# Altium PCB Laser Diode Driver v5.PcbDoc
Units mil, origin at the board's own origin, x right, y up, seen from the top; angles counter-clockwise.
Board outline 12450 x 4500 mil, 6 copper layers (Top Layer, Internal Plane 1, Internal Plane 2, Internal Plane 3, Internal Plane 4, Bottom Layer); 217 components, 97 nets, 592 pads, 132 vias.
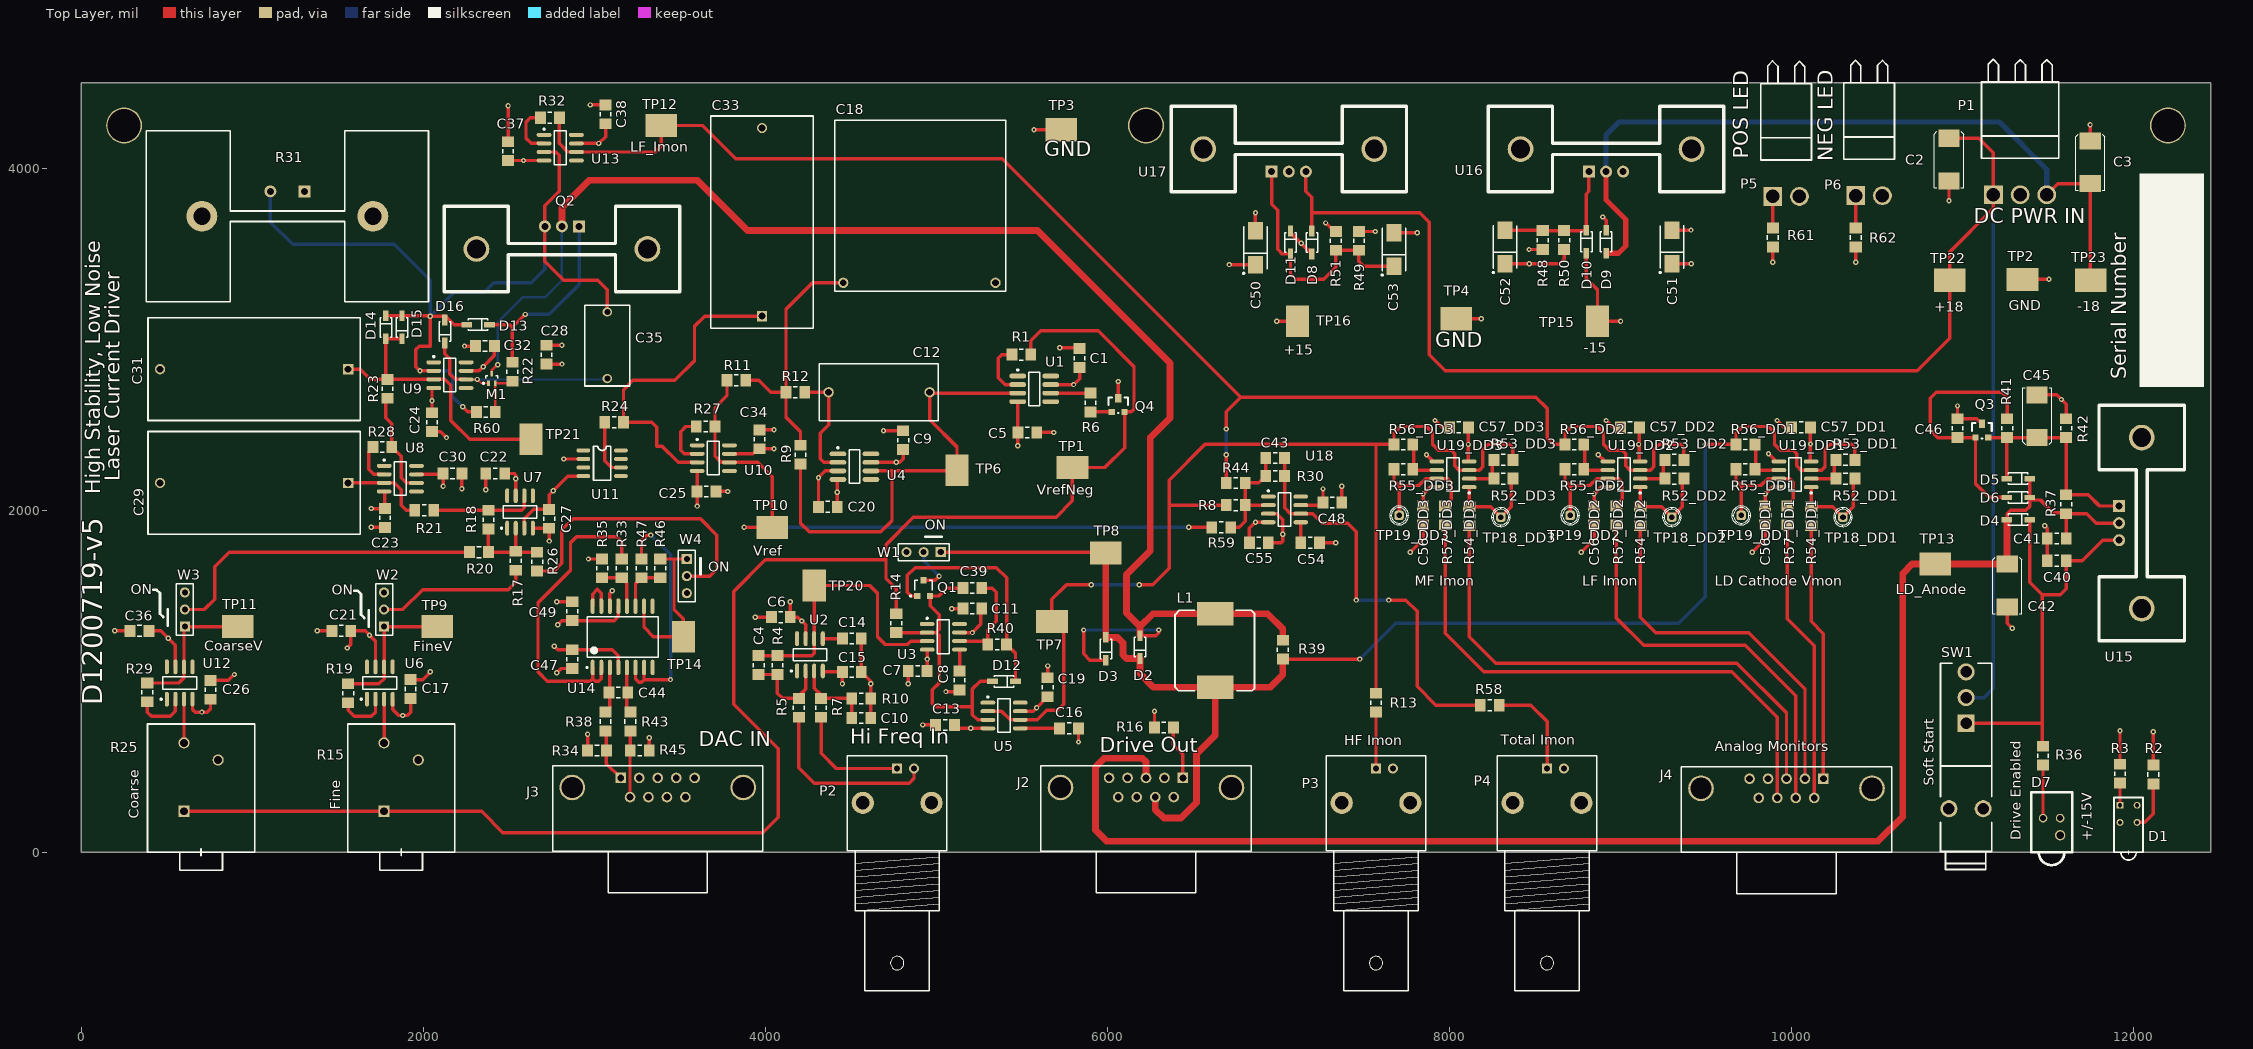
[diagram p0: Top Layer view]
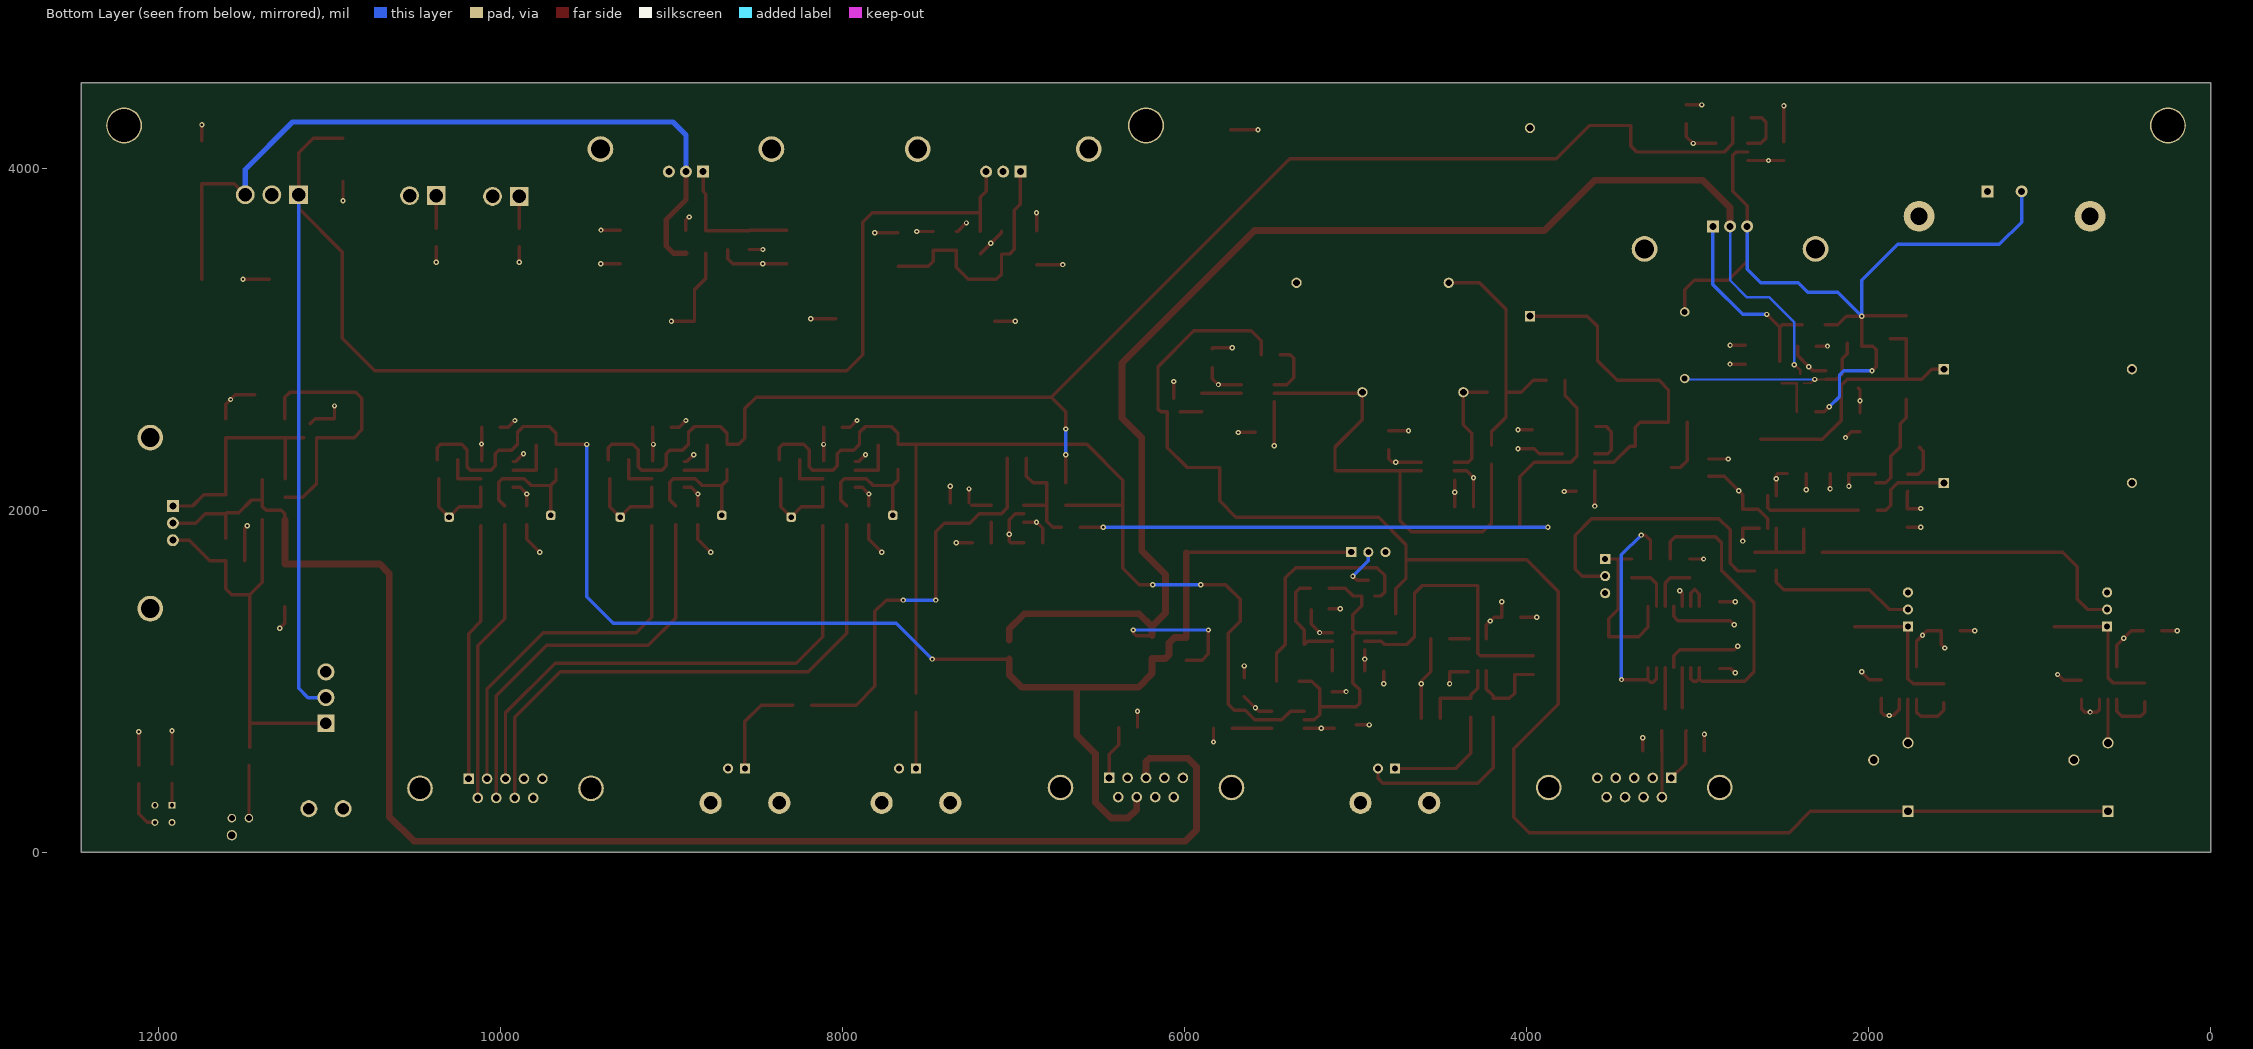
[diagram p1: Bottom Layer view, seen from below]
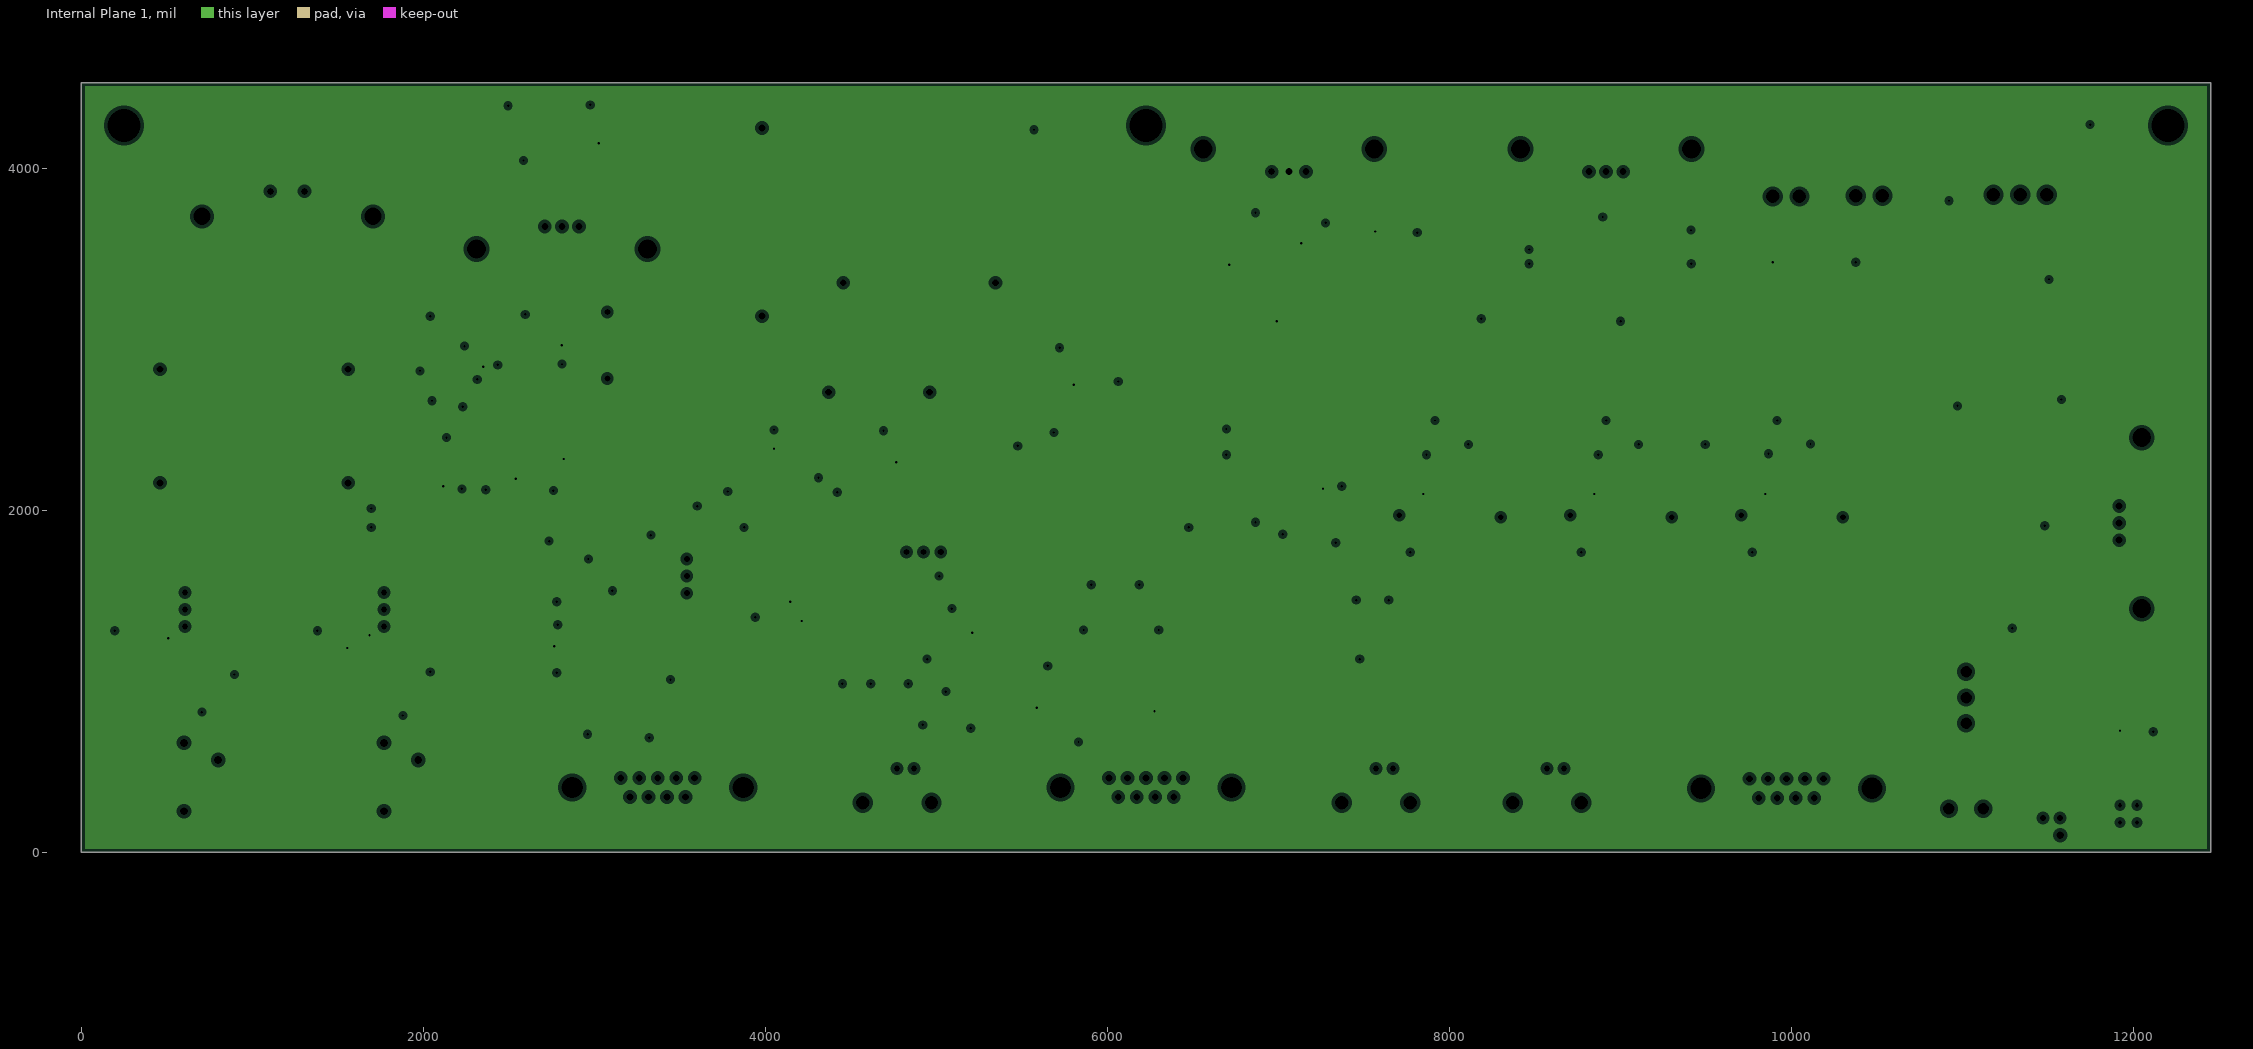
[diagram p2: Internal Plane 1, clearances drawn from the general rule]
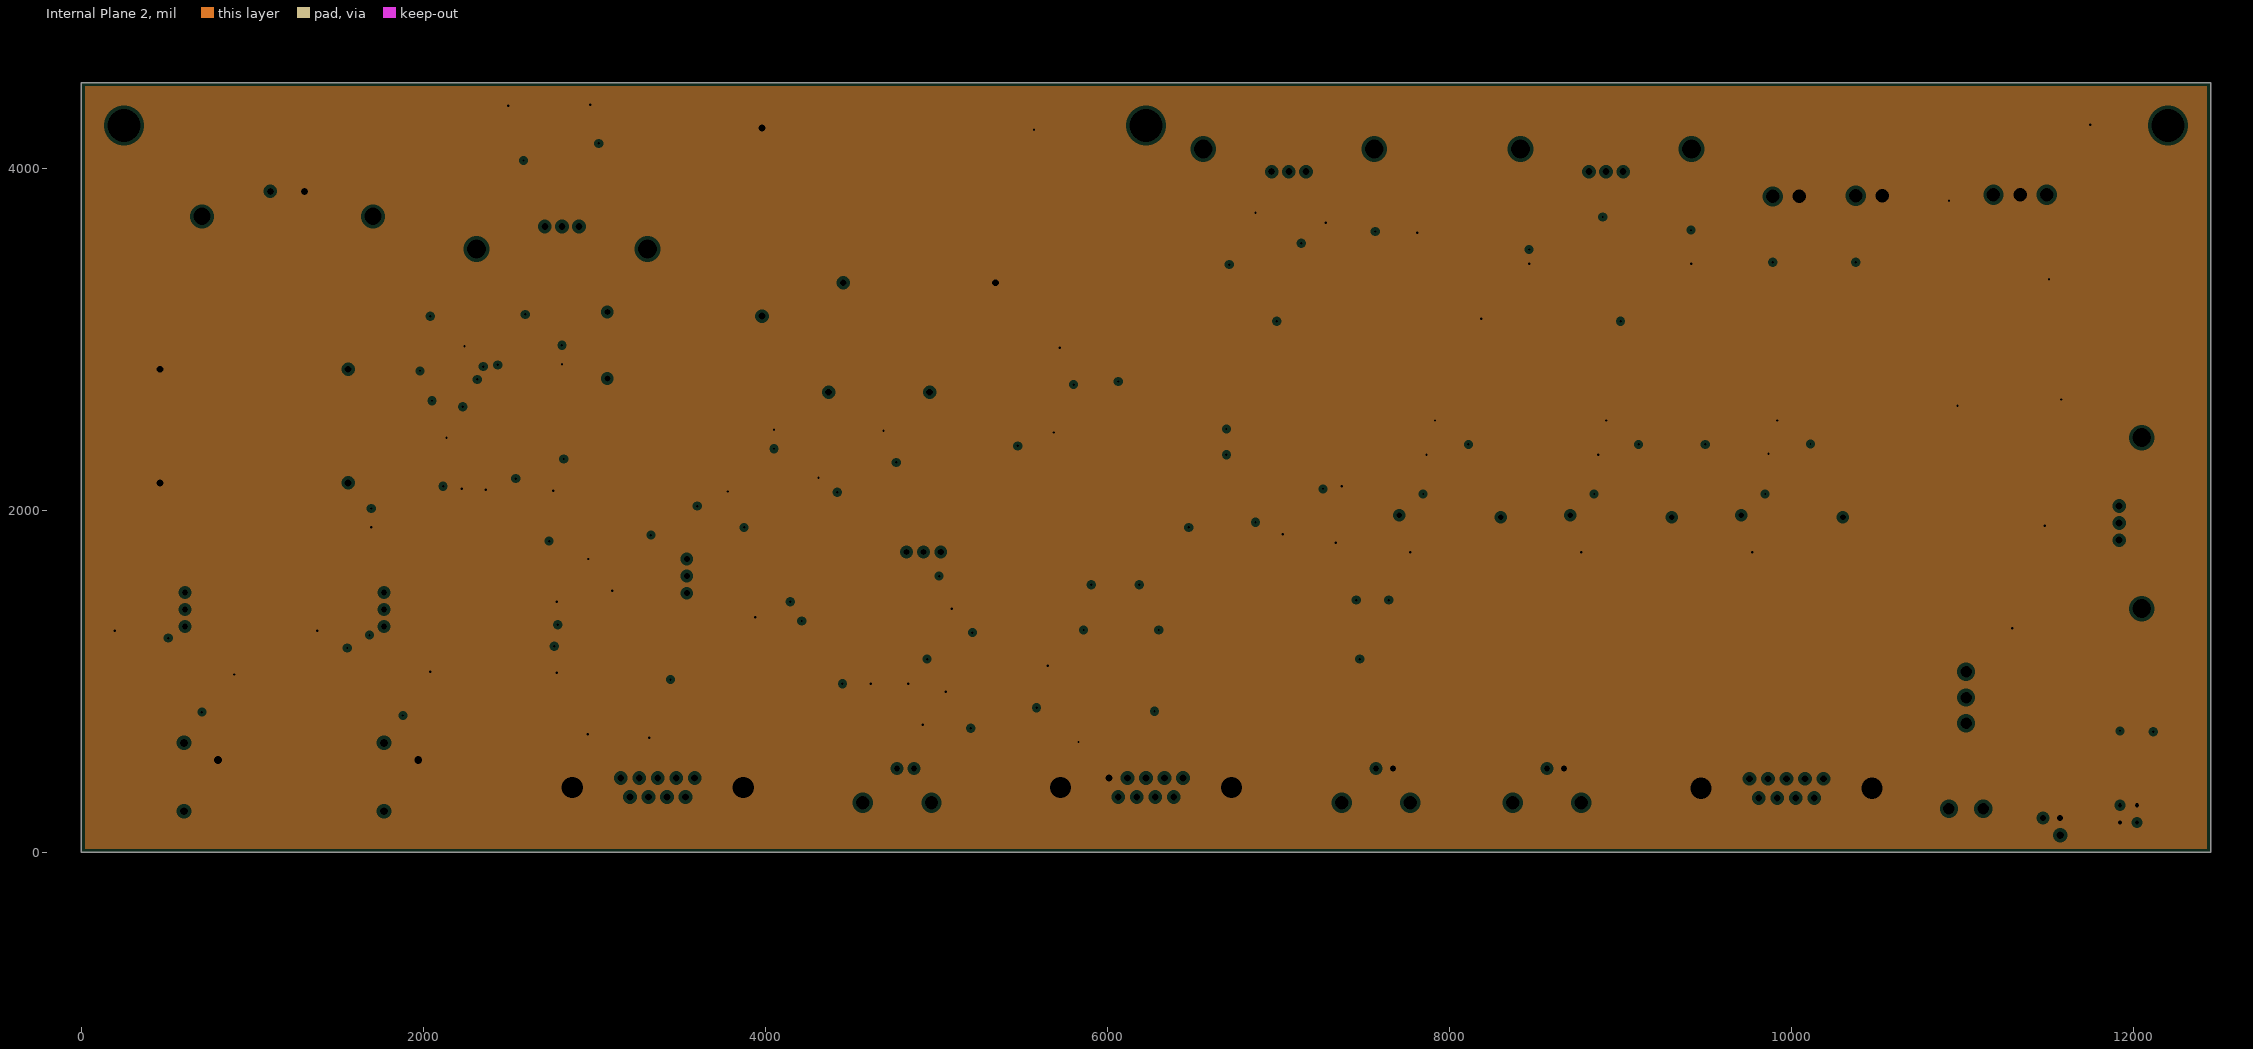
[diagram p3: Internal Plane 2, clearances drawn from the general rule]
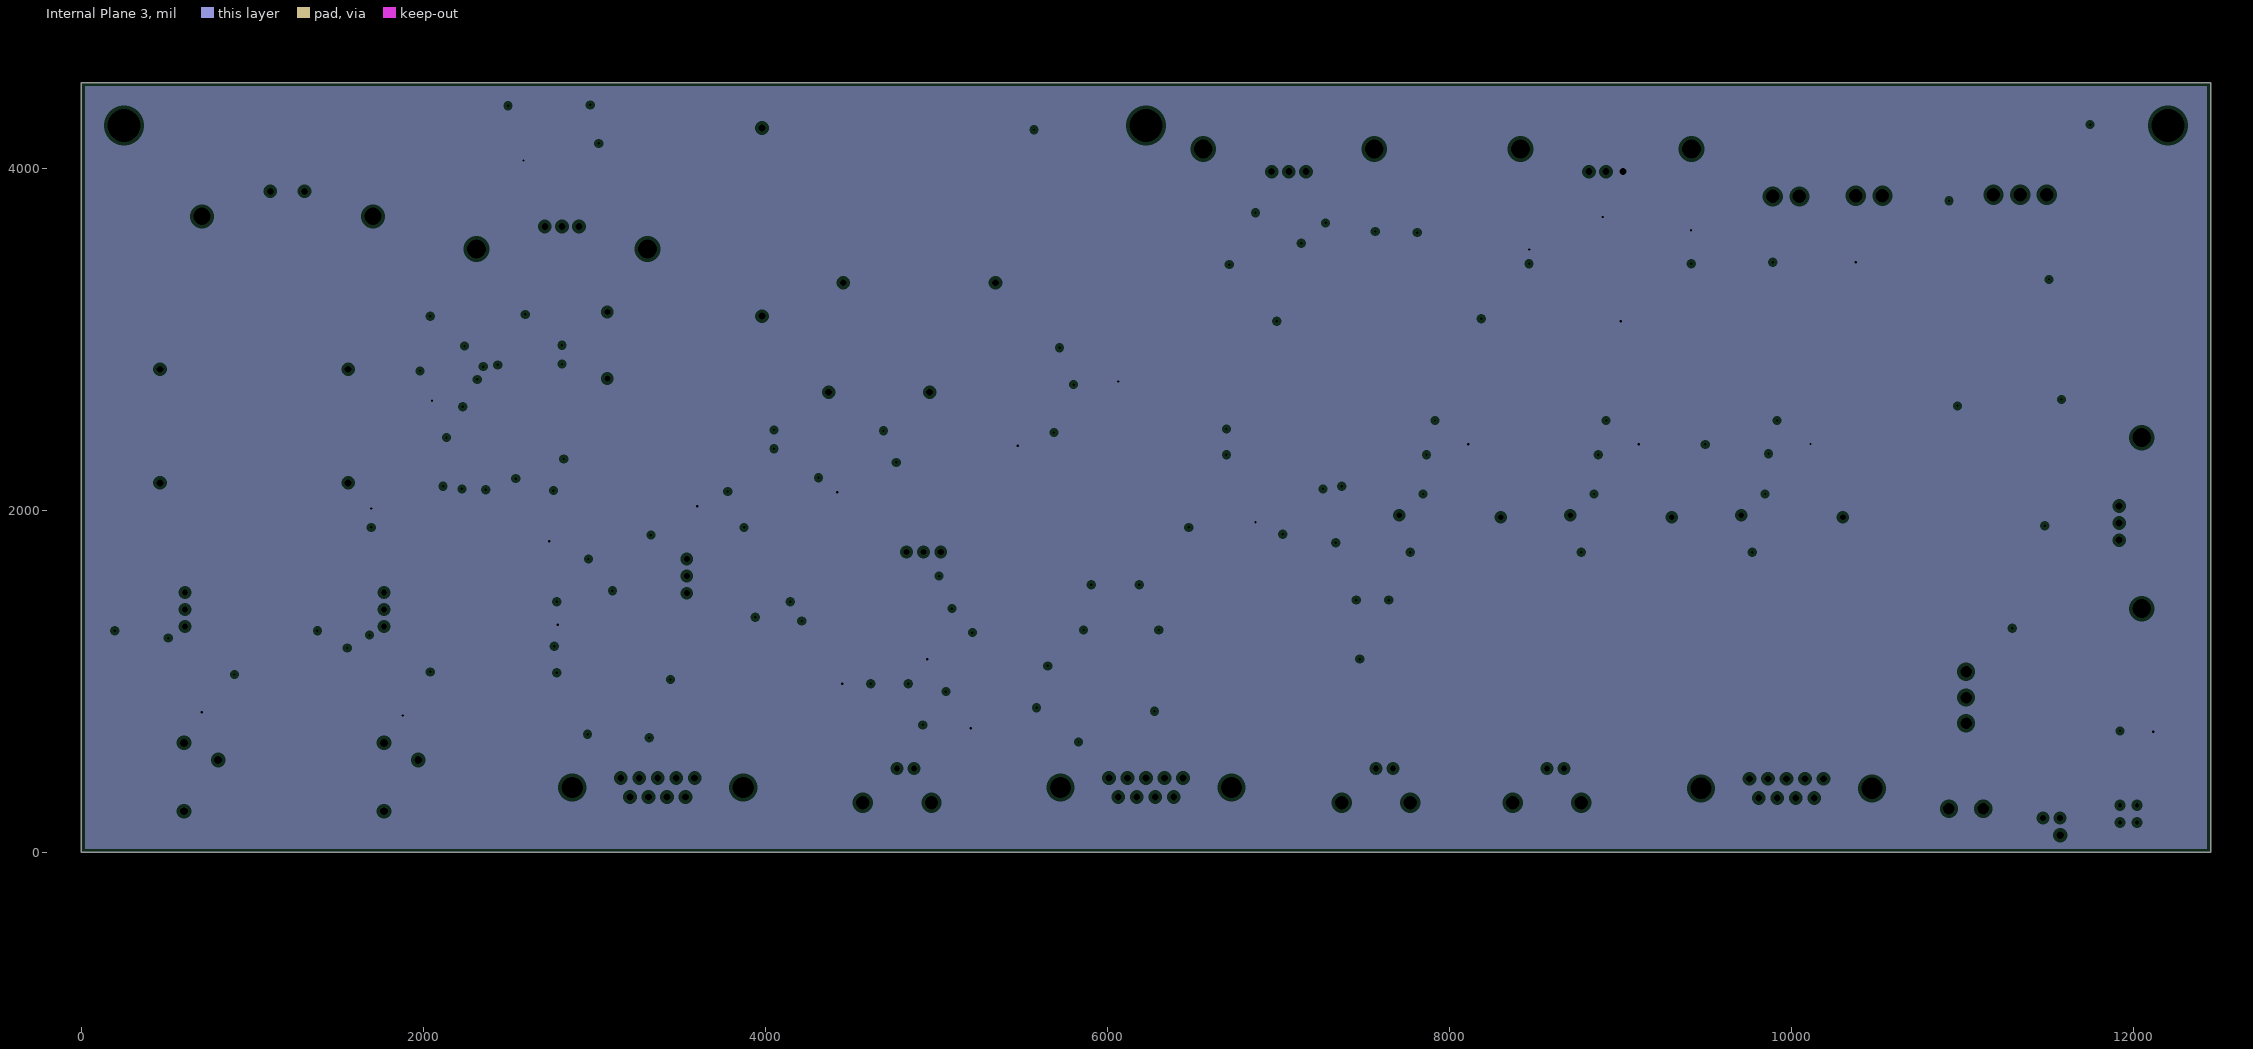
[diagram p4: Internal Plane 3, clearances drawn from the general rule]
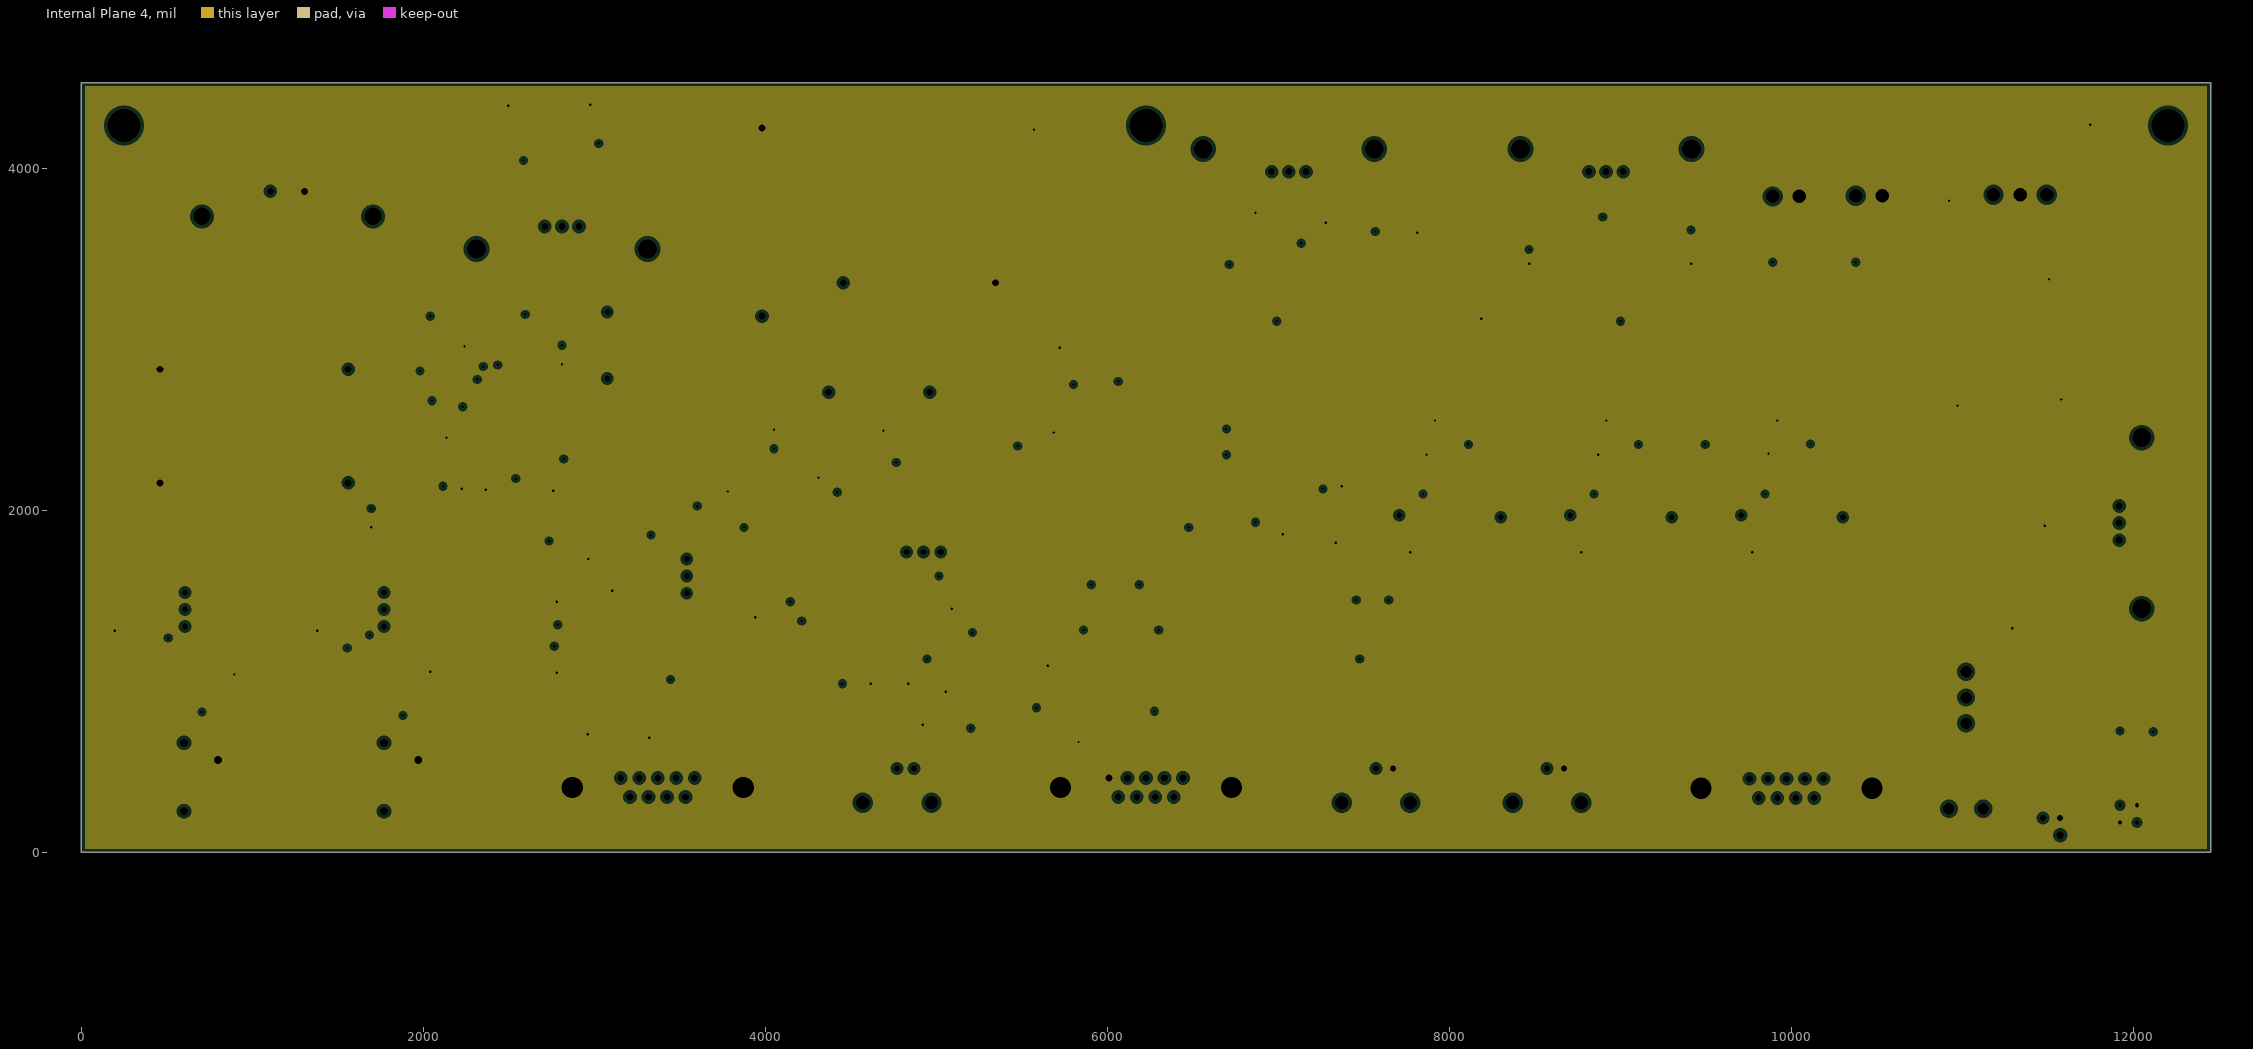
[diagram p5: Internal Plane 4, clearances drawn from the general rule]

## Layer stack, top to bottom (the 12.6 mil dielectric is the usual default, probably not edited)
Top Layer: signal copper 1.4
Dielectric: core 12.6, FR-4, Dk 4.8
Internal Plane 1: plane copper 1.4, net +15
Dielectric: prepreg 12.6, FR-4, Dk 4.8
Internal Plane 2: plane copper 1.4, net GND
Dielectric: core 12.6, FR-4, Dk 4.8
Internal Plane 3: plane copper 1.4, net -15
Dielectric: prepreg 12.6, FR-4, Dk 4.8
Internal Plane 4: plane copper 1.4, net GND
Dielectric: core 12.6, FR-4, Dk 4.8
Bottom Layer: signal copper 1.4

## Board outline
0,0 12450,0 12450,4500 0,4500

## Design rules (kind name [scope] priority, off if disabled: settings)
Clearance [All] p1: gap=10
Height [All] p1: minheight=0 maxheight=2000 prefheight=500
HoleSize [All] p1: absolutevalues=TRUE maxlimit=200 minlimit=14 maxpercent=80.000 minpercent=20.000
MinimumSolderMaskSliver [All] p1: minsoldermaskwidth=5
PlaneClearance [All] p1: clearance=20
PlaneConnect [All] p1: planeconnectstyle=Relief reliefexpansion=20 reliefentries=4 reliefconductorwidth=10 reliefairgap=10
PolygonConnect [All] p1: connectstyle=Relief reliefconductorwidth=10 reliefentries=4 polygonreliefangle="90 Angle" airgapwidth=10
RoomDefinition "Laser Diode Driver v5" [InComponentClass('Laser Diode Driver v5')] p1 off: confinementstyle=ConfineIn formatcopy=TRUE lockcomponents=FALSE outline 10015,3275 10245,3275 10245,3470 10015,3470
RoomDefinition DD3 [InComponentClass('DD3')] p2: confinementstyle=ConfineIn formatcopy=TRUE lockcomponents=FALSE outline 7555,1655 8430,1655 8430,2555 7555,2555
RoomDefinition DD2 [InComponentClass('DD2')] p3: confinementstyle=ConfineIn formatcopy=TRUE lockcomponents=FALSE outline 8555,1655 9430,1655 9430,2555 8555,2555
RoomDefinition DD1 [InComponentClass('DD1')] p4: confinementstyle=ConfineIn formatcopy=TRUE lockcomponents=FALSE outline 9555,1655 10430,1655 10430,2555 9555,2555
RoutingVias [All] p1: holewidth=14 width=31 viastyle="Through Hole" minholewidth=14 minwidth=31 maxholewidth=50 maxwidth=50
SilkscreenOverComponentPads [All] p1: minsilkscreentomaskgap=5
SolderMaskExpansion [All] p1: expansion=4
Width [All] p1: maxlimit=100 minlimit=10 preferedwidth=20
22 further rules are at their usual default settings.

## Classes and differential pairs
channel class DiffDriver: DD1 DD2 DD3
component class "Laser Diode Driver v5": C1 C2 C3 C4 C5 C6 C7 C8 C9 C10 C11 C12 C13 C14 C15 C16 C17 C18 C19 C20 C21 C22 C23 C24 C25 C26 C27 C28 C29 C30 C31 C32 C33 C34 C35 C36 C37 C38 C39 C40 C41 C42 C43 C44 C45 C46 C47 C48 C49 C50 C51 C52 C53 C54 C55 D1 D2 D3 D4 D5 D6 D7 D8 D9 D10 D11 D12 D13 D14 D15 D16 J2 J3 J4 L1 M1 P1 P2 P3 P4 P5 P6 Q1 Q2 Q3 Q4 R1 R2 R3 R4 R5 R6 R7 R8 R9 R10 R11 R12 R13 R14 R15 R16 R17 R18 R19 R20 R21 R22 R23 R24 R25 R26 R27 R28 R29 R30 R31 R32 R33 R34 R35 R36 R37 R38 R39 R40 R41 R42 R43 R44 R45 R46 R47 R48 R49 R50 R51 R58 R59 R60 R61 R62 SW1 TP1 TP2 TP3 TP4 TP6 TP7 TP8 TP9 TP10 TP11 TP12 TP13 TP14 TP15 TP16 TP20 TP21 TP22 TP23 U1 U2 U3 U4 U5 U6 U7 U8 U9 U10 U11 U12 U13 U14 U15 U16 U17 U18 W1 W2 W3 W4
component class DD3: C56_DD3 C57_DD3 R52_DD3 R53_DD3 R54_DD3 R55_DD3 R56_DD3 R57_DD3 TP18_DD3 TP19_DD3 U19_DD3
component class DD2: C56_DD2 C57_DD2 R52_DD2 R53_DD2 R54_DD2 R55_DD2 R56_DD2 R57_DD2 TP18_DD2 TP19_DD2 U19_DD2
component class DD1: C56_DD1 C57_DD1 R52_DD1 R53_DD1 R54_DD1 R55_DD1 R56_DD1 R57_DD1 TP18_DD1 TP19_DD1 U19_DD1

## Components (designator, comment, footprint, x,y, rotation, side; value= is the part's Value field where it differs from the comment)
C1 "1UF" 3216[1206] 5836.46,2890 r270 top
C2 "10UF Tantalum, 35V" 7343-31 10920,4175 r90 top
C3 "10UF Tantalum, 35V" 7343-31 11745,4160 r90 top
C4 "4.7pF" 3216[1206] 3960,1095 r270 top
C5 "1UF" 3216[1206] 5531.46,2455 r180 top
C6 "1UF" 3216[1206] 4090,1375 r0 top
C7 "1UF" 3216[1206] 4890,1060 r0 top
C8 "68pF" 3216[1206] 5135,1005 r90 top
C9 "1UF" 3216[1206] 4805,2410 r90 top
C10 "4.7pF" 3216[1206] 4560,785 r180 top
C11 "1UF" 3216[1206] 5210,1425 r0 top
C12 "2.7UF" ECQ-E1275KF 4960,2690 r180 top
C13 "1UF" 3216[1206] 5050,745 r0 top
C14 "27pF" 3216[1206] 4505,1250 r180 top
C15 "1UF" 3216[1206] 4505,1055 r180 top
C16 "68pF" 3216[1206] 5775,725 r180 top
C17 "1UF" 3216[1206] 1925,955 r270 top
C18 "10UF" ECQ-E1106KF_Side 4455,3330 r0 top
C19 "1UF" 3216[1206] 5650,965 r270 top
C20 "1UF" 3216[1206] 4365,2020 r180 top
C21 "1UF" 3216[1206] 1520,1295 r0 top
C22 "1UF" 3216[1206] 2420,2215 r0 top
C23 "1UF" 3216[1206] 1775,1955 r90 top
C24 "1UF" 3216[1206] 2050,2515 r90 top
C25 "1UF" 3216[1206] 3655,2110 r180 top
C26 "1UF" 3216[1206] 755,950 r270 top
C27 "1UF" 3216[1206] 2735,1950 r270 top
C28 "100nF" 3216[1206] 2720,2910 r90 top
C29 "20uF" AmCap_20UF 1560,2160 r180 top
C30 "1UF" 3216[1206] 2170,2215 r180 top
C31 "20uF" AmCap_20UF 1560,2825 r180 top
C32 "1UF" 3216[1206] 2360,2960 r0 top
C33 "20uF" AmCap_20UF 3980,3135 r90 top
C34 "1UF" 3216[1206] 3965,2415 r270 top
C35 "1UF" ECQ-E1105KF 3075,3160 r270 top
C36 "1UF" 3216[1206] 340,1295 r0 top
C37 "1UF" 3216[1206] 2495,4100 r270 top
C38 "1UF" 3216[1206] 3065,4315 r270 top
C39 "100pF" 3216[1206] 5210,1545 r180 top
C40 "1UF" 3216[1206] 11550,1705 r180 top
C41 "100nF" 3216[1206] 11550,1835 r180 top
C42 "22uF" 7343-31 11260,1685 r90 top
C43 "4.7pF" 3216[1206] 6980,2305 r180 top
C44 "5.6nF" 3216[1206] 3140,935 r180 top
C45 "10uF" 7343-31 11435,2425 r270 top
C46 "1UF" 3216[1206] 10970,2480 r90 top
C47 "1UF" 3216[1206] 2870,1130 r270 top
C48 "1UF" 3216[1206] 7315,2045 r180 top
C49 "1UF" 3216[1206] 2870,1410 r90 top
C50 "10UF Tantalum, 35V" 6032 6865,3535 r90 top
C51 "10UF Tantalum, 35V" 6032 9300,3540 r90 top
C52 "10UF Tantalum, 35V" 6032 8325,3540 r90 top
C53 "10UF Tantalum, 35V" 6032 7675,3525 r90 top
C54 "68pF" 3216[1206] 7185,1810 r180 top
C55 "1UF" 3216[1206] 6885,1810 r180 top
C56_DD1 "1UF" 3216[1206] 9845,1970 r90 top (schematic designator C56)
C56_DD2 "1UF" 3216[1206] 8845,1970 r90 top (schematic designator C56)
C56_DD3 "1UF" 3216[1206] 7845,1970 r90 top (schematic designator C56)
C57_DD1 "1UF" 3216[1206] 10055,2485 r0 top (schematic designator C57)
C57_DD2 "1UF" 3216[1206] 9055,2485 r0 top (schematic designator C57)
C57_DD3 "1UF" 3216[1206] 8055,2485 r0 top (schematic designator C57)
D1 "DUAL_LED" "MY LUMEX DUAL LED" 11970,0 r90 top
D2 "RB160M-60" SOD123 6190,1200 r270 top
D3 "RB160M-60" SOD123 5990,1190 r270 top
D4 "RB160M-60" SOD123 11325,1945 r0 top
D5 "RB160M-60" SOD123 11325,2185 r0 top
D6 "RB160M-60" SOD123 11325,2075 r0 top
D7 "LED-GREEN" LED_RA 11520,0 r0 top
D8 "RB160M-60" SOD123 7195,3565.32 r90 top
D9 "RB160M-60" SOD123 8915,3570 r90 top
D10 "RB160M-60" SOD123 8800,3570 r90 top
D11 "RB160M-60" SOD123 7070,3565.32 r90 top
D12 "RB160M-60" SOD123 5395,1000 r0 top
D13 "RB160M-60" SOD123 2320,3085 r0 top
D14 "RB160M-60" SOD123 1780,3070 r90 top
D15 "RB160M-60" SOD123 1875,3070 r270 top
D16 "RB160M-60" SOD123 2125,3045 r270 top
J2 "D Connector 9" MY_DB9F_RA 6225,435 r180 top
J3 "Male D9" MY_DB9M_RA 3370,435 r180 top
J4 "D9 Female" MY_DB9F_RA 9970,430 r180 top
L1 "Inductor" CDRH127 6630,965 r180 top
M1 "NMOS" SOT416-3L 2400,2770 r90 top
P1 "Header 3" Molex_156_RA_3 11180,3845 r90 top
P2 "BNC" "MY_BNC_RA CON" 4770,490 r90 top
P3 "BNC" "MY_BNC_RA CON" 7570,490 r90 top
P4 "BNC" "MY_BNC_RA CON" 8570,490 r90 top
P5 "Header 2" MOLEX_156_RA_2 9890,3835 r90 top
P6 "Header 2" MOLEX_156_RA_2 10375,3840 r90 top
Q1 "2N5551" SOT-23 4925,1545 r0 top
Q2 "2N6292" HS403-ND 2810,3660 r180 top
Q3 "PN2907A" "sot-23 3906" 11115,2460 r0 top
Q4 "2N2907" "sot-23 3906" 6065,2610 r0 top
R1 "499" 3216[1206] 5496.46,2910 r180 top
R2 "2K" 3216[1206] 12115,455 r270 top
R3 "2K" 3216[1206] 11920,460 r90 top
R4 "1K" 3216[1206] 4070,1095 r270 top
R5 "1K" 3216[1206] 4195,845 r270 top
R6 "1K" 3216[1206] 5900,2630 r90 top
R7 "1K" 3216[1206] 4325,845 r90 top
R8 "499k" 3216[1206] 6750,2030 r180 top
R9 "43.2K" 3216[1206] 4205,2325 r270 top
R10 "1K" 3216[1206] 4560,900 r0 top
R11 "43.2K" 3216[1206] 3830,2760 r0 top
R12 "24.3K" 3216[1206] 4175,2690 r180 top
R13 "499" 3216[1206] 7570,875 r270 top
R14 "4.99k" 3216[1206] 4765,1340 r270 top
R15 "10k" "Bournes Pot" 1870,0 r0 top
R16 "2.1k" 3216[1206] 6330,730 r180 top
R17 "100k" 3216[1206] 2540,1705 r90 top
R18 "10K" 3216[1206] 2380,1945 r90 top
R19 "499" 3216[1206] 1560,930 r270 top
R20 "10K" 3216[1206] 2325,1755 r0 top
R21 "10K" 3216[1206] 2005,2000 r180 top
R22 "1k" 3216[1206] 2520,2810 r270 top
R23 "10K" 3216[1206] 1790,2710 r90 top
R24 "10K" 3216[1206] 3115,2515 r0 top
R25 "10k" "Bournes Pot" 700,0 r0 top
R26 "10K" 3216[1206] 2665,1700 r90 top
R27 "499" 3216[1206] 3650,2490 r180 top
R28 "499" 3216[1206] 1760,2370 r180 top
R29 "499" 3216[1206] 385,935 r270 top
R30 "10K" 3216[1206] 6980,2200 r180 top
R31 "Res3" "AAVID TO220 Heatsink_2pin" 1205,3865 r180 top
R32 "499" 3216[1206] 2740,4295 r180 top
R33 "3.01K" 3216[1206] 3160,1660 r90 top
R34 "100K OHM" 3216[1206] 3015,595 r0 top
R35 "3.01k" 3216[1206] 3045,1660 r90 top
R36 "2K" 3216[1206] 11470,565 r270 top
R37 "249" 3216[1206] 11605,2035 r270 top
R38 "1K" 3216[1206] 3065,765 r270 top
R39 "OMIT" 3216[1206] 7025,1185 r270 top
R40 "1k" 3216[1206] 5355,1215 r180 top
R41 "1K" 3216[1206] 11260,2480 r90 top
R42 "2.21k" 3216[1206] 11605,2480 r270 top
R43 "1K" 3216[1206] 3210,765 r270 top
R44 "10k" 3216[1206] 6750,2160 r180 top
R45 "100K OHM" 3216[1206] 3265,595 r0 top
R46 "3.01k" 3216[1206] 3385,1660 r270 top
R47 "3.01K" 3216[1206] 3275,1660 r90 top
R48 "120" 3216[1206] 8545,3580 r270 top
R49 "249" 3216[1206] 7470,3575 r90 top
R50 "1.3K" 3216[1206] 8670,3580 r90 top
R51 "2.7K" 3216[1206] 7335,3575 r270 top
R52_DD1 "4.99K" 3216[1206] 10315,2185 r0 top (schematic designator R52)
R52_DD2 "4.99K" 3216[1206] 9315,2185 r0 top (schematic designator R52)
R52_DD3 "4.99K" 3216[1206] 8315,2185 r0 top (schematic designator R52)
R53_DD1 "4.99K" 3216[1206] 10315,2295 r180 top (schematic designator R53)
R53_DD2 "4.99K" 3216[1206] 9315,2295 r180 top (schematic designator R53)
R53_DD3 "4.99K" 3216[1206] 8315,2295 r180 top (schematic designator R53)
R54_DD1 "0 Ohm" 3216[1206] 10115,1965 r270 top (schematic designator R54)
R54_DD2 "0 Ohm" 3216[1206] 9115,1965 r270 top (schematic designator R54)
R54_DD3 "0 Ohm" 3216[1206] 8115,1965 r270 top (schematic designator R54)
R55_DD1 "4.99K" 3216[1206] 9730,2240 r180 top (schematic designator R55)
R55_DD2 "4.99K" 3216[1206] 8730,2240 r180 top (schematic designator R55)
R55_DD3 "4.99K" 3216[1206] 7730,2240 r180 top (schematic designator R55)
R56_DD1 "4.99K" 3216[1206] 9730,2385 r0 top (schematic designator R56)
R56_DD2 "4.99K" 3216[1206] 8730,2385 r0 top (schematic designator R56)
R56_DD3 "4.99K" 3216[1206] 7730,2385 r0 top (schematic designator R56)
R57_DD1 "0 Ohm" 3216[1206] 9975,1970 r270 top (schematic designator R57)
R57_DD2 "0 Ohm" 3216[1206] 8975,1970 r270 top (schematic designator R57)
R57_DD3 "0 Ohm" 3216[1206] 7975,1970 r270 top (schematic designator R57)
R58 "499" 3216[1206] 8235,860 r0 top
R59 "499k" 3216[1206] 6665,1900 r180 top
R60 "1k" 3216[1206] 2365,2575 r180 top
R61 "2K" 3216[1206] 9890,3595 r270 top
R62 "2K" 3216[1206] 10375,3595 r270 top
SW1 "SPDT" my_ra_spdt 11020,755 r90 top
TP1 "TESTPT" smt_tp 5795,2250 r180 top
TP2 "TESTPT" smt_tp 11350,3350 r180 top
TP3 "TESTPT" smt_tp 5730,4225 r180 top
TP4 "TESTPT" smt_tp 8040,3120 r180 top
TP6 "TESTPT" smt_tp 5120,2235 r90 top
TP7 "TESTPT" smt_tp 5675,1350 r180 top
TP8 "TESTPT" smt_tp 5990,1750 r180 top
TP9 "TESTPT" smt_tp 2080,1320 r180 top
TP10 "TESTPT" smt_tp 4040,1900 r0 top
TP11 "TESTPT" smt_tp 915,1320 r180 top
TP12 "TESTPT" smt_tp 3390,4250 r0 top
TP13 "TESTPT" smt_tp 10840,1685 r180 top
TP14 "TESTPT" smt_tp 3520,1260 r90 top
TP15 "TESTPT" smt_tp 8865,3105 r270 top
TP16 "TESTPT" smt_tp 7110,3105 r90 top
TP18_DD1 "Wire Hole" TP-hole 10300,1960 r90 top (schematic designator TP18)
TP18_DD2 "Wire Hole" TP-hole 9300,1960 r90 top (schematic designator TP18)
TP18_DD3 "Wire Hole" TP-hole 8300,1960 r90 top (schematic designator TP18)
TP19_DD1 "Wire Hole" TP-hole 9705,1970 r90 top (schematic designator TP19)
TP19_DD2 "Wire Hole" TP-hole 8705,1970 r90 top (schematic designator TP19)
TP19_DD3 "Wire Hole" TP-hole 7705,1970 r90 top (schematic designator TP19)
TP20 "TESTPT" smt_tp 4285,1560 r90 top
TP21 "TESTPT" smt_tp 2630,2415 r270 top
TP22 "TESTPT" smt_tp 10925,3345 r0 top
TP23 "TESTPT" smt_tp 11750,3345 r0 top
U1 "ADOP27AQ" SO8_M 5571.46,2710 r0 top
U2 "AD829" SOIC127P600-8N 4260,1155 r90 top
U3 "AD829" SOIC127P600-8N 5040,1260 r0 top
U4 "OPA140AID" SO8_M 4520,2255 r0 top
U5 "AD829" SOIC127P600-8N 5395,800 r0 top
U6 "OP27GS" SO-8_N 1745,990 r90 top
U7 "OP27GS" SO-8_N 2565,1990 r90 top
U8 "OP27GS" SO-8_N 1865,2185 r0 top
U9 "OP27GS" SO-8_N 2155,2790 r0 top
U10 "OP27GS" SO-8_N 3695,2305 r0 top
U11 "LT1021" SO-8 3055,2290 r0 top
U12 "OP27GS" SO-8_N 575,990 r90 top
U13 "OP27GS" SO-8_N 2800,4120 r0 top
U14 "LT1125CS" SOIC127P1030-16N 3165,1260 r90 top
U15 "LM317T" HS403-ND 11915,1925 r270 top
U16 "LM337BT" HS403-ND 8915,3980 r0 top
U17 "LM317T" HS403-ND 7060,3980 r0 top
U18 "AD829" SOIC127P600-8N 7035,2005 r0 top
U19_DD1 "AD8672" SO8_N 10020,2210 r180 top (schematic designator U19)
U19_DD2 "AD8672" SO8_N 9020,2210 r180 top (schematic designator U19)
U19_DD3 "AD8672" SO8_N 8020,2210 r180 top (schematic designator U19)
W1 "Jumper" HDR1X3 5025,1755 r180 top
W2 "Jumper" HDR1X3 1770,1320 r90 top
W3 "Jumper" HDR1X3 605,1320 r90 top
W4 "Jumper" HDR1X3 3540,1715 r270 top

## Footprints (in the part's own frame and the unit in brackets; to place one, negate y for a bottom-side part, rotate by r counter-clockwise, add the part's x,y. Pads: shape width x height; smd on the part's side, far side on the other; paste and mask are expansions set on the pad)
3216[1206] [mm] "Chip Resistor; Body 3.2 x 1.6 mm (LxW typ)"
  rect 1.6x1.8 smd: 1(-1.4,0) 2(1.4,0)
  silkscreen extent -0.3,-0.8 0.3,0.8, body extent -2.29,-1.02 2.29,1.02, height 0.48
6032 [mm] "Capacitor, SM Tantalum; Body 6.0 x 3.2 mm (LxW typ)"
  rect 2.6x2.2 smd: 1(-2.5,0) 2(2.5,0)
  silkscreen extent -3.92,-1.75 3.15,1.87
7343-31 [mil]
  rect 100x125 smd: 1(0,0) 2(-250,0)
  silkscreen extent -290,-85 40,85
"AAVID TO220 Heatsink_2pin" [mil] "High Power TO220 Heatsink with two pins"
  rect 70x70 hole 40.5: 1(-100,0)
  round 70 hole 40.5: 2(100,0)
  round 180 hole 100.5: 4(-500,146) 5(500,146)
  silkscreen extent -825,-354 825,646
AmCap_20UF [mil] "American Capacitor Radial Lead 20UF, 35 volt"
  rect 60x60 hole 40: 1(0,0)
  round 60 hole 40: 2(1100,0)
  silkscreen extent -70,-300 1170,300
"Bournes Pot" [mil] "Model 83 Series Bournes Boardmount Potentiometer"
  round 65 hole 46: 1(100,540) 2(-100,640)
  rect 65x65 hole 46: 3(-100,240)
  silkscreen extent -313,-105 313,750
CDRH127 [mil] "CDRH127 series power inductor footprint."
  rect 215x135 smd: 1(0,0) 2(0,-430)
  silkscreen extent -230,-450 235,20
ECQ-E1105KF [mil] "Plastic Cap 1UF"
  round 55 hole 35: 1(0,0) 2(390,0)
  silkscreen extent -39,-132 433,132
ECQ-E1106KF_Side [mil] "Plastic Cap 10UF (On Side)"
  round 60 hole 40: 1(0,0) 2(890,0)
  silkscreen extent -50,-50 950,950
ECQ-E1275KF [mil] "Plastic Cap 2.7UF"
  round 60 hole 40: 1(0,0) 2(590.55,0)
  silkscreen extent -50,-167 645,167
HDR1X3 [mm] "Connector; Header; 3 Position"
  rect 1.5x1.5 hole 0.9: 1(0,0)
  round 1.5 hole 0.9: 2(2.54,0) 3(5.08,0)
  silkscreen extent -1.27,-1.27 6.35,1.27
HS403-ND [mil] "Aavid 513002B02500G Heatsink for TO220"
  rect 70x70 hole 40.5: 1(-100,0)
  round 70 hole 40.5: 2(0,0) 3(100,0)
  round 150 hole 110: 4(-500,132) 5(500,132)
  silkscreen extent -688,-118 688,382
LED_RA [mil]
  round 60 hole 45: 0(50,100)
  round 50 hole 35: A(-50,200) K(50,200)
  silkscreen extent -120,-75 120,350
MOLEX_156_RA_2 [mil] "2 Pin Molex, 0.156mil Spacing, Right Angle"
  rect 110x110 hole 79: 1(0,0)
  round 110 hole 79: 2(0,-156)
  silkscreen extent 213,-226 792,70
Molex_156_RA_3 [mil] "3 Pin Molex, 0.156mil Spacing, Right Angle"
  rect 110x110 hole 79: 1(0,0)
  round 110 hole 79: 2(0,-156) 3(0,-312)
  silkscreen extent 213,-382 792,70
"MY LUMEX DUAL LED" [mil] "Stacked Dual LED PCB Rt Angle"
  rect 40x40 hole 25: 1(275,50)
  round 40 hole 25: 2(275,-50) 3(175,50) 4(175,-50)
  silkscreen extent -45,-85 320,85
"MY_BNC_RA CON" [mm] "Connector; BNC Elbow"
  rect 1.5x1.5 hole 0.9: 1(0,0)
  round 1.5 hole 0.9: 2(0,-2.5)
  round 3.3 hole 2: 3(-5.1,5.1) 4(-5.1,-5.1)
  silkscreen extent -33,-7.4 1.9,7.4
MY_DB9F_RA [mil]
  rect 62x62 hole 40: 1(-216,0)
  round 62 hole 40: 2(-108,0) 3(0,0) 4(108,0) 5(216,0) 6(-162,112) 7(-54,112) 8(54,112) 9(162,112)
  round 150 hole 125: 10(-500,56) 11(500,56)
  silkscreen extent -615,-70 615,672
MY_DB9M_RA [mil]
  rect 62x62 hole 40: 1(216,0)
  round 62 hole 40: 2(108,0) 3(0,0) 4(-108,0) 5(-216,0) 6(162,112) 7(54,112) 8(-54,112) 9(-162,112)
  round 150 hole 125: 10(-500,56) 11(500,56)
  silkscreen extent -615,-70 615,672
my_ra_spdt [mil] "PCB RA SPDT"
  rect 100x100 hole 67: 1(0,0)
  round 100 hole 67: 2(150,0) 3(300,0) 4(-500,100) 5(-500,-100)
  silkscreen extent -855,-150 350,150
smt_tp [mil] "5016 Surface Mount Test Point"
  rect 185x135 smd: 1(0,0)
SO8_M [mm] "SOIC, 8-Leads, Body 4.9x3.9mm, Pitch 1.27mm, IPC Low Density"
  oval 2.5x0.7 smd: 1(-2.45,1.905) 2(-2.45,0.635) 3(-2.45,-0.635) 4(-2.45,-1.905) 5(2.45,-1.905) 6(2.45,-0.635) 7(2.45,0.635) 8(2.45,1.905)
  silkscreen extent -2.57,-2.5 0.8,2.93, body extent -2,-2.5 2,2.5, height 1.75
SO8_N [mm] "SOIC, 8-Leads, Body 4.9x3.9mm, Pitch 1.27mm, IPC Medium Density"
  oval 2.2x0.6 smd: 1(-2.4,1.905) 2(-2.4,0.635) 3(-2.4,-0.635) 4(-2.4,-1.905) 5(2.4,-1.905) 6(2.4,-0.635) 7(2.4,0.635) 8(2.4,1.905)
  silkscreen extent -2.53,-2.5 0.9,2.88, body extent -2,-2.5 2,2.5, height 1.75
SO-8 [mil] "Small Outline 8-pin IC"
  oval 80x24 smd: 1(-120,60) 2(-120,10) 3(-120,-40) 4(-120,-90) 5(100,-90) 6(100,-40) 7(100,10) 8(100,60)
  silkscreen extent -60,-115 40,85
SO-8_N [mm] "SOIC, 8-Leads, Body 4.9x3.9mm, Pitch 1.27mm, IPC Medium Density"
  oval 2.2x0.6 smd: 1(-2.4,1.905) 2(-2.4,0.635) 3(-2.4,-0.635) 4(-2.4,-1.905) 5(2.4,-1.905) 6(2.4,-0.635) 7(2.4,0.635) 8(2.4,1.905)
  silkscreen extent -2.52,-2.5 0.9,2.88, body extent -1.95,-2.45 1.95,2.45, height 1.75
SOD123 [mm] "SOD-123; 2 Leads; Body 2.7 x 1.6 mm, (LxW)"
  rect 1.6x0.8 smd: 1(-1.7,0) 2(1.7,0)
  silkscreen extent -1.45,-0.85 1.45,0.85
SOIC127P600-8N [mm] "SOIC, 8-Leads, Body 4.9x3.9mm, Pitch 1.27mm, IPC Medium Density"
  oval 2.2x0.6 smd: 1(-2.4,1.905) 2(-2.4,0.635) 3(-2.4,-0.635) 4(-2.4,-1.905) 5(2.4,-1.905) 6(2.4,-0.635) 7(2.4,0.635) 8(2.4,1.905)
  silkscreen extent -2.52,-2.5 0.9,2.88, body extent -2,-2.5 2,2.5, height 1.75
SOIC127P1030-16N [mm] "SOIC, 16-Leads, Body 10.3x7.5mm, Pitch 1.27mm, IPC Medium Density"
  oval 2.3x0.6 smd: 1(-4.55,4.445) 2(-4.55,3.175) 3(-4.55,1.905) 4(-4.55,0.635) 5(-4.55,-0.635) 6(-4.55,-1.905) 7(-4.55,-3.175) 8(-4.55,-4.445) 9(4.55,-4.445) 10(4.55,-3.175) 11(4.55,-1.905) 12(4.55,-0.635) 13(4.55,0.635) 14(4.55,1.905) 15(4.55,3.175) 16(4.55,4.445)
  silkscreen extent -4.67,-5.25 3,5.42, body extent -3.75,-5.25 3.75,5.25, height 2.65
SOT416-3L [mm] "SOT416, 3-Leads, Body 1.6x0.8mm, Pitch 0.50mm, Lead Span 1.6mm, IPC High Density"
  rect 0.8x0.4 smd: 1(-0.7,0.5) 2(-0.7,-0.5) 3(0.7,0)
  silkscreen extent -0.82,-0.9 0.45,1.37, body extent -0.45,-0.9 0.45,0.9, height 0.95
SOT-23 [mm] "SOT-23; 3 Leads; Body 3.1 x 2.5 mm, inc. leads (LxW max)"
  rect 0.9x0.95 smd: 1(-0.95,-1.175) 2(0.95,-1.175) 3(0,1.175)
  silkscreen extent -2.07,-1.3 1.3,1.18
"sot-23 3906" [mil]
  rect 36x36 smd: 1(35,-35) 2(-40,-35)
  rect 36x50 smd: 3(-2,45)
  silkscreen extent -60,-40 55,50
TP-hole [mil] "Pad for small test point"
  rrect50% 55x55 hole 33: 1(0,0)
  silkscreen extent -55,-55 55,55

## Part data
C1 C5 C9 C12 C18 C20 C56_DD1 C56_DD2 C56_DD3 C57_DD1 C57_DD2 C57_DD3: library part MYCAP
C2 C3 C29 C31 C33 C42 C45 C50 C51 C52 C53: library part "CAPACITOR POL", "Polarized Cap"
C4 C6 C7 C8 C10 C11 C13 C14 C15 C16 C17 C19 C21 C22 C23 C24 C25 C26 C27 C28 C30 C32 C34 C35 C36 C37 C38 C39 C40 C41 C43 C46 C48 C54 C55: library part Cap, "Capacitor"
C44 C47 C49: library part MYCAP, "CAP 1.0UF 50V CERAMIC F 1206"
D1: "Dual Led indicator"
D2 D3 D4 D5 D6 D12 D13 D14 D15 D16: library part "Diode 1N4001", "1 Amp General Purpose Rectifier"
D7: library part LED, "LED GREEN T1-3/4 RT ANG PCB"
D8 D9 D10 D11: library part "Diode 1N4148", "High Conductance Fast Diode"
J2: "Receptacle Assembly, 9 Position, Right Angle"
J3 J4: library part "D Connector 9", "Receptacle Assembly, 9 Position, Right Angle"
M1: library part 2SK3019, "ROHM N-Channel MOSFET"
P1: "Header, 3-Pin"
P5 P6: "Header, 2-Pin"
Q1: "NPN General Purpose Amplifier"
Q2: library part FZT649, "SOT223 NPN Silicon Planar High-Performance Transistor"
Q3: "PNP General Purpose Amplifier"
Q4: library part 2N3906, "PNP General Purpose Amplifier"
R1 R2 R3 R4 R5 R6 R7 R8 R9 R10 R11 R12 R13 R14 R16 R17 R18 R19 R20 R21 R22 R23 R24 R26 R27 R28 R29 R30 R32 R36 R37 R39 R40 R41 R42 R44 R52_DD1 R52_DD2 R52_DD3 R53_DD1 R53_DD2 R53_DD3 R54_DD1 R54_DD2 R54_DD3 R55_DD1 R55_DD2 R55_DD3 R56_DD1 R56_DD2 R56_DD3 R57_DD1 R57_DD2 R57_DD3 R58 R59 R60 R61 R62: library part Res3, "Resistor"
R15 R25: library part MPEPOT, "Potentiometer"
R31: "Resistor"
R33 R34 R35 R38 R43 R45 R46 R47: library part MYRES, "Resistor"
R48 R49 R50 R51: library part MYRES
SW1: library part MY_SPDT, "Rocker SPDT"
TP1 TP2 TP3 TP4 TP6 TP7 TP8 TP9 TP10 TP11 TP12 TP13 TP14 TP15 TP16 TP20 TP21 TP22 TP23: "PCB Testpoint"
TP18_DD1 TP18_DD2 TP18_DD3 TP19_DD1 TP19_DD2 TP19_DD3: library part TestHole, "Plated Hole to Solder Wire to"
U1: "Ultra-Low Noise, Precision Operational Amplifier"
U2 U3 U5 U18: library part OP184ES, "Video Operational Amplifier"
U4: library part ADOP27AQ, "FET Input Operational Amplifier"
U6 U7 U8 U9 U10 U12 U13: "Low-Noise, Precision Operational Amplifier"
U11: "Precision Voltage Reference"
U14: "Quad Low Noise, High-Speed Precision Operational Amplifier"
U15 U17: "Three-Terminal Adjustable Output Positive Voltage Regulator"
U16: "3-Terminal Adjustable Negative Voltage Regulator"
U19_DD1 U19_DD2 U19_DD3: library part AD826AR, "High-Speed, Low-Power Dual Operational Amplifier"
W1 W2 W3 W4: "Jumper Wire"

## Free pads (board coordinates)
  round 210 hole 193: 8(250,4250) 8(12200,4250) 9(6225,4250)

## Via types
v1: diameter 31, hole 14, Top Layer to Bottom Layer, 132 vias

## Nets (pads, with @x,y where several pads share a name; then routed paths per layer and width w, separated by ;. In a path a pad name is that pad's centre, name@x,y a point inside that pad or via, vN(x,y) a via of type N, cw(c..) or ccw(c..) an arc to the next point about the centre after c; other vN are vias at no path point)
+15: C1.2 C6.2 C9.1 C11.2 C19.2 C21.2 C22.2 C28.2 C30.2 C32.2 C34.2 C36.2 C38.2 C47.1 C48.2 C50.1 C56_DD1.2 C56_DD2.2 C56_DD3.2 D8.1 D11.2 R3.2 R16.2 R49.2 R61.2 TP16.1 U1.7 U2.7 U3.7 U4.7 U5.7 U6.7 U7.7 U8.7 U9.7 U10.7 U11.2 U12.7 U13.7 U14.4 U17.2 U18.7 U19_DD1.8 U19_DD2.8 U19_DD3.8 | length 5458.7
  Top Layer w20: C36.2 465,1295 550,1210 U12.7 ; v1(1555,1195) 1575.12,1215.12 C21.2 1660,1295 1720,1235 U6.7 ; U8.7 C30.2@2109.88,2210 ; v1(2114.88,2139.88) C30.2 ; U9.7 2325,2815 v1(2350,2840) 2415.12,2905.12 C32.2 ; C22.2 2530,2215 2540,2205 U7.7 ; C28.2 v1(2809.88,2965.12) ; v1(2765,1205) 2784.88,1185.12 C47.1 3104.88,1185.12 3140,1150 U14.4 ; v1(2820,2300) U11.2 ; U13.7 v1(3025,4145) 3065,4185 C38.2 ; U10.7 3925,2330 3954.88,2359.88 C34.2 v1(4049.88,2359.88) ; v1(4145.12,1464.88) C6.2 4190,1375 4235,1330 U2.7 ; U4.7 4785,2280 4805,2300 C9.1 ; U3.7 v1(5210,1285) 5260,1335 C11.2@5260,1419.88 ; U5.7 5565.12,825 C19.2 ; U1.7 v1(5801.46,2735) 5836.46,2770 C1.2 ; R16.2 v1(6274.88,824.88) ; v1(6711.57,3436.57) C50.1 ; v1(6990,3105) TP16.1 ; D11.2 7070,3623.39 D8.1 ; U18.7 C48.2@7244.88,2030 ; C48.2 v1(7259.88,2124.88) ; R49.2 v1(7564.88,3630.12) ; C56_DD3.2 v1(7845,2095) 7885,2135 U19_DD3.8 ; C56_DD2.2 v1(8845,2095) 8885,2135 U19_DD2.8 ; C56_DD1.2 v1(9845,2095) 9885,2135 U19_DD1.8 ; v1(9890,3450) R61.2 ; R3.2 v1(11920,710)
  other v1: 5585.12,845 507.5,1252.5 1685,1270 4212.5,1352.5 2540,2185 4765,2280 7132.5,3560.89
+18: C2.1 D8.2 P1.1 SW1.2 TP22.1 U17.3 | length 9563.8
  Top Layer w20: U17.3 7160,3865 7195,3830 7195,3735 ; D8.2 7195,3735 ; C2.1 11095,4175 11180,4090 P1.1 11180,3765 10925,3510 TP22.1 10925,3005 10735,2815 7975,2815 7880,2910 7880,3685 7825,3740 7200,3740 7195,3735
  Bottom Layer w20: SW1.2 11125,905 11180,960 P1.1
-15: C5.2 C7.2 C13.2 C15.2 C17.2 C20.1 C23.2 C24.2 C25.2 C26.2 C27.2 C37.2 C49.1 C51.2 C55.2 C57_DD1.2 C57_DD2.2 C57_DD3.2 D9.2 D10.1 Q4.3 R2.1 R48.2 R62.2 TP15.1 U1.4 U2.4 U3.4 U4.4 U5.4 U6.4 U7.4 U8.4 U9.4 U10.4 U12.4 U13.4 U14.13 U16.3 U18.4 U19_DD1.4 U19_DD2.4 U19_DD3.4 | length 4766.1
  Top Layer w20: U12.4 650,835 665,820 735,820 755,840 C26.2 ; v1(1695.12,2010.12) C23.2 1775,2105.51 U8.4 ; U6.4 1820,835 1855,800 1905,800 1925,820 C17.2 ; C24.2 2050,2704.49 U9.4 ; C37.2@2495.12,4045 U13.4 ; U7.4 C27.2@2734.37,1895.51 ; v1(2735,1820) C27.2 ; v1(2785,1330) 2809.88,1354.88 C49.1 3114.88,1354.88 3140,1380 U14.13 ; v1(3600.51,2024.49) U10.4 ; U2.4@4340.51,1055 C15.2 v1(4449.88,985.12) ; C20.1 U4.4@4420.12,2176.57 ; C7.2 U3.4@4945.12,1184.61 ; C13.2@5125.12,725 U5.4 ; v1(5475,2376.46) U1.4 ; Q4.3 v1(6063,2753) ; C55.2 6829.88,1894.88 v1(6865,1930) U18.4 ; U19_DD3.4@8110.12,2289.37 C57_DD3.2 ; v1(8464.88,3524.88) R48.2 ; D10.1 8800,3355 8865,3290 TP15.1 v1(9000,3105) ; v1(8895,3715) 8915,3695 D9.2 ; U19_DD2.4@9110.12,2289.37 C57_DD2.2 ; C51.2 v1(9411.57,3638.43) ; U19_DD1.4@10110.12,2289.37 C57_DD1.2 ; v1(10375,3450) R62.2 ; R2.1 v1(12115,705)
  other v1: 5200,725 1880,800 705,820 4945.12,1130 4420,2105 8110.12,2385 9105,2385 10110.12,2387.19 2050,2640 2585,4045
-18: C3.2 D9.1 P1.3 TP23.1 U16.2 | length 4540.7
  Top Layer w20: P1.3 11557,3910 C3.2 TP23.1@11745,3350
  Top Layer w30: D9.1 8988.07,3503.07 9030,3545 9030,3700 8915,3815 U16.2
  Bottom Layer w30: U16.2 8915,4195 8990,4270 11215,4270 11492,3993 P1.3
GND: C1.1 C2.2 C3.1 C5.1 C6.1 C7.1 C8.1 C9.2 C10.1 C11.1 C13.1 C14.1 C15.1 C16.1 C17.1 C18.2 C19.1 C20.2 C21.1 C22.1 C23.1 C24.1 C25.1 C26.1 C27.1 C28.1 C29.2 C30.1 C31.2 C32.1 C33.2 C34.1 C36.1 C37.1 C38.1 C40.2 C41.2 C42.2 C45.2 C46.2 C47.2 C48.1 C49.2 C50.2 C51.1 C52.1 C53.2 C54.1 C55.1 C56_DD1.1 C56_DD2.1 C56_DD3.1 C57_DD1.1 C57_DD2.1 C57_DD3.1 D1.2 D1.3 D7.K J2.5 J2.10 J2.11 J3.10 J3.11 J4.10 J4.11 P1.2 P3.2 P4.2 P5.2 P6.2 Q3.3 R10.2 R15.1 R25.1 R31.1 R34.1 R35.2 R42.1 R45.2 R50.1 R51.1 TP2.1 TP3.1 TP4.1 U4.3 U7.3 U11.4 U14.14 U18.3 U19_DD1.5 U19_DD2.5 U19_DD3.5 | length 8185
  Top Layer w20: v1(195,1295) C36.1 ; C26.1 860.12,1005.12 v1(895,1040) ; v1(1380,1295) C21.1 ; v1(1695.12,1899.88) C23.1 ; C17.1 1995.12,1010.12 v1@2045,1060 ; C24.1 2100.12,2459.88 v1(2135,2425) ; v1@2225.12,2119.88 C30.1 ; v1(2240,2960) C32.1 ; v1(2364.88,2120.12) C22.1 ; C37.1 v1(2495,4365) ; U7.3 2590,1950 2645.12,2005.12 C27.1 2735,2090 v1(2760,2115) 2845,2200 U11.4 ; C28.1 v1(2810.12,2854.88) ; v1(2780,1050) 2804.88,1074.88 C47.2 ; v1(2780.12,1465.12) C49.2 ; R34.1 v1(2959.88,689.88) ; v1(2964.88,1715.12) R35.2 ; v1(2974.88,4370.12) C38.1 ; U14.14 3090,1515 v1(3105,1530) ; R45.2 v1(3320.12,669.88) ; C25.1 v1(3780,2110) ; v1(3940,1375) C6.1 ; C34.1 v1(4049.88,2470.12) ; C20.2 v1(4309.88,2189.88) 4350,2230 U4.3 ; C14.1 C15.1 4615.12,1000 R10.2 C10.1 ; v1(4690.12,2465.12) C9.2 ; v1(4834.88,985.12) C7.1 ; v1(4920,745) C13.1 ; v1(5055.12,940) C8.1@5135,940 ; v1(5090,1425) C11.1 ; v1(5570,4225) TP3.1 ; C5.1 v1(5686.46,2455) ; C19.1 v1(5650,1090) ; v1(5720,2950) 5835,2950 5836.46,2948.54 C1.1 ; v1(5830.12,645.12) C16.1 ; C50.2 v1(6865,3740) ; C55.1 7015,1810 7025,1820 7025,1945 6990,1980 U18.3 ; C54.1 v1(7335,1810) ; v1(7275,3680) 7324.88,3630.12 R51.1 ; C48.1 v1(7370.12,2139.88) ; C53.2 v1(7811.57,3623.43) ; v1(7770,1755) 7845,1830 C56_DD3.1 ; v1(7865,2325) 7905,2285 U19_DD3.5 ; v1(7915,2525) 7955,2485 C57_DD3.1 ; TP4.1 v1(8185,3120) ; C52.1 8641.57,3441.57 8670,3470 R50.1 ; v1(8770,1755) 8845,1830 C56_DD2.1 ; v1(8870,2325) 8910,2285 U19_DD2.5 ; v1(8915,2525) 8955,2485 C57_DD2.1 ; C51.1 v1(9413.43,3441.57) ; v1(9770,1755) 9845,1830 C56_DD1.1 ; v1(9865,2330) 9910,2285 U19_DD1.5 ; v1(9915,2525) 9955,2485 C57_DD1.1 ; v1(10920,3810) C2.2 ; v1(10970,2610) C46.2 11082.88,2535.12 Q3.3 ; C42.2 11260,1340 v1(11290,1310) ; TP2.1 v1(11505,3350) ; C45.2 11550,2675 11605,2620 R42.1 ; v1(11480,1910) 11494.88,1895.12 C41.2 C40.2 ; C3.1 v1(11745,4255)
  other v1: 4615.12,985 2040,1055 7025,1860 2225.12,2125 11577.5,2647.5 8465,3441.57
HF_IMON: R8.2 R13.1 R53_DD3.1 R56_DD3.1 TP7.1 U5.2 U5.6 U19_DD3.3 | length 6771
  Top Layer w20: U5.2 5380,825 5430,775 U5.6 5590,775 5645,830 5710,830 5745,865 5745,1280 TP7.1 5675,1480 5760,1565 v1(5905,1565) ; v1(6185,1565) 6265,1565 6360,1660 6360,2175 6570,2385 7570,2385 ; 6365,2030 R8.2 ; R13.1 7570,2385 ; R53_DD3.1 8370.12,2364.88 8350,2385 8225,2385 8195,2355 8195,2255 8175,2235 U19_DD3.3 8055,2235 8030,2260 8030,2330 8010,2350 7935,2350 7900,2385 7900,2455 7865,2490 7715,2490 7674.88,2449.88 R56_DD3.1 7570,2385
  Bottom Layer w20: v1(5905,1565) v1(6185,1565)
LD_CATHODE: D2.2 D3.1 J2.7 L1.1 R39.2 R53_DD1.1 R56_DD1.1 TP8.1 U19_DD1.3 W1.1 | length 8768.9
  Top Layer w20: W1.1 TP8.1@5985,1755 ; R39.2 7474.88,1129.88 v1(7475,1130) ; v1(9495,2385) R56_DD1.1 9674.88,2449.88 9715,2490 9865,2490 9900,2455 9900,2385 9935,2350 10010,2350 10030,2330 10030,2260 10055,2235 U19_DD1.3 10175,2235 10195,2255 10195,2355 10225,2385 10350,2385 10370.12,2364.88 R53_DD1.1
  Top Layer w40: TP8.1 D3.1 6058.07,1256.93 6090,1225 6090,1155 6111.93,1133.07 D2.2 6190,1045 6270,965 L1.1 ; J2.7 6279,251 6330,200 6430,200 6520,290 6520,575 6630,685 L1.1 ; R39.2 7025,1040 6950,965 L1.1
  Bottom Layer w20: v1(7475,1130) 7685,1340 9340,1340 9495,1495 v1(9495,2385)
LF_IMON: R32.1 R44.2 R53_DD2.1 R56_DD2.1 TP12.1 U13.6 U19_DD2.3 | length 8758.6
  Top Layer w20: R32.1 2795.12,4144.88 2845,4095 U13.6 3355,4095 3390,4130 TP12.1 3630,4250 3825,4055 5385,4055 6780,2660 ; R44.2 6694.88,2324.88 v1(6695,2325) ; v1(6695,2475) 6695,2575 6780,2660 ; R53_DD2.1 9370.12,2364.88 9350,2385 9225,2385 9195,2355 9195,2255 9175,2235 U19_DD2.3 9055,2235 9030,2260 9030,2330 9010,2350 8935,2350 8900,2385 8900,2455 8865,2490 8715,2490 8674.88,2449.88 R56_DD2.1 8605,2385 8570,2420 8570,2595 8505,2660 6780,2660
  Bottom Layer w20: v1(6695,2325) v1(6695,2475)
NetC4_1: C4.1 R4.1 TP20.1 U2.6 U3.3 | length 1687.2
  Top Layer w20: C4.1 R4.1 4270.12,1150.12 4285,1165 U2.6 TP20.1 4610,1560 4655,1515 4655,1260 4700,1215 4830,1215 4850,1235 U3.3
NetC4_2: C4.2 R4.2 R5.1 U2.2 | length 534.2
  Top Layer w20: C4.2 R4.2 4070,930 4099.88,900.12 R5.1 4195,915 4235,955 U2.2
NetC8_2: C8.2 U3.5 | length 124.4
  Top Layer w20: C8.2 U3.5@5135,1184.49
NetC10_2: C10.2 R7.2 R10.1 U2.3 | length 471.7
  Top Layer w20: U2.3 4285,960 4325,920 R7.2 4504.77,900.12 C10.2@4504.77,785.12
NetC12_1: C12.1 R9.2 TP6.1 U1.3 U4.6 | length 2747.3
  Top Layer w20: R9.2 4205,1925 4255,1875 4675,1875 4740,1940 4740,2230 ; U4.6 4740,2230 ; C12.1 4960,2530 5120,2370 TP6.1 ; C12.1@4965,2685 U1.3 ; TP6.1@5115,2230 4740,2230
NetC12_2: C12.2 R12.1 U4.2 | length 661.6
  Top Layer w20: R12.1 C12.2 4369.45,2499.45 4320,2450 4320,2300 4340,2280 U4.2
NetC14_2: C14.2 U2.5 | length 114.4
  Top Layer w20: U2.5@4335.51,1250 C14.2
NetC16_2: C16.2 U5.5 | length 230.4
  Top Layer w20: U5.5 C16.2
NetC18_1: C18.1 R9.1 R11.2 R12.2 | length 1493.1
  Top Layer w20: R11.2 3960,2760 4030,2690 R12.2 ; R9.1 4205,2460 4119.88,2545.12 R12.2 ; C18.1 4275,3330 4119.88,3174.88 R12.2
NetC29_1: C29.1 R21.2 U8.3 | length 508.9
  Top Layer w20: C29.1 U8.3 1830,2160 1870,2120 1870,2030 1900,2000 R21.2
NetC31_1: C31.1 D14.1 D15.2 R23.2 TP21.1 U9.3 | length 1697
  Top Layer w20: C31.1 1630,2825 1690,2765 U9.3 2125,2765 2160,2730 2160,2525 2270,2415 TP21.1 ; R23.2 1780,2775.12 D14.1 D15.2
NetC33_1: C33.1 R24.2 U10.3 | length 1887.4
  Top Layer w20: U10.3 3490,2280 3395,2375 3365,2375 3365,2485 3335,2515 R24.2 3170.12,2705.12 3225,2760 3470,2760 3585,2875 3585,3075 3645,3135 C33.1
NetC35_1: C35.1 D13.1 D14.2 D15.1 D16.1 Q2.3 R31.2 R60.2 U9.2 U13.3 | length 5297.2
  Top Layer w20: D14.2 D15.1 2038.07,3136.93 v1(2040,3135) ; U9.2 v1(1980,2815) 1955,2840 1955,2940 1975,2960 2039.88,2960 2040,2960.12 v1(2040,3135) ; v1(2230,2605) 2260,2575 R60.2 ; D13.1 2180,3085 2130,3135 v1(2040,3135) ; U13.3 2775,4095 2795,4075 2795,3865 2710,3780 Q2.3 2710,3455 2820,3345 3020,3345 3075,3290 C35.1
  Bottom Layer w20: R31.2 1105,3685 1235,3555 1830,3555 2040,3345 v1(2040,3135) 2180,3275 2355,3275 2410,3330 2630,3330 2710,3410 Q2.3 ; v1(1980,2815) 2145,2815 2170,2790 2170,2665 v1(2230,2605)
NetC35_2: C35.2 D16.2 M1.1 U9.6 | length 1204.7
  Top Layer w10: U9.6 v1(2315,2765) 2337.56,2742.44 M1.1
  Top Layer w20: D16.2 2125,2915 2155,2885 2155,2795 2185,2765 U9.6
  Bottom Layer w10: v1(2315,2765) 3070,2765 C35.2
NetC39_1: C39.1 R40.2 U3.6 | length 594.7
  Top Layer w20: U3.6 5279.88,1235 R40.2 5299.88,1299.88 5350,1350 5350,1520 5325,1545 C39.1
NetC39_2: C39.2 D12.1 Q1.2 R14.2 U3.2 U5.3 | length 1761
  Top Layer w20: R14.2@4765.12,1285 U3.2 4995,1285 ; C39.2 5060,1545 5013.74,1498.74 Q1.2 4962.4,1442.6 5015,1390 5015,1305 4995,1285 ; U5.3 5240,775 5210,805 5210,850 ; D12.1 5255,1000 5210,955 5210,850 ; 4995,1285 5000,1285 5015,1270 5015,990 4975,950 4975,870 4995,850 5210,850
NetC40_1: C40.1 D4.2 R36.1 SW1.1 U15.3 | length 2484.4
  Top Layer w20: SW1.1 11465,755 ; D4.2 11391.93,1578.07 11465,1505 ; R36.1@11465,615 11465,755 ; U15.3 11820,1825 11700,1705 C40.1 11605.12,1540.12 11570,1505 11465,1505 ; 11465,755 11465,1505
NetC41_1: C41.1 C42.1 D4.1 D5.2 D6.2 J2.3 R37.2 TP13.1 U15.2 | length 8974.9
  Top Layer w20: D4.1@11260,1943.07 11260,1980 11280,2000 11370,2000 11391.93,2021.93 D6.2@11391.93,2060 ; D5.2@11391.93,2180 D6.2@11391.93,2060 ; C41.1 R37.2@11605.12,1979.76 ; U15.2 11780,1925 11725.12,1979.88 R37.2 11599.88,1985 11530,1985 11455,2060 D6.2@11391.93,2060
  Top Layer w40: J2.3 6225,530 6205,550 5980,550 5930,500 5930,130 5995,65 10505,65 10650,210 10650,1630 10705,1685 TP13.1 C42.1 D4.1@11260,1943.07
NetC43_1: C43.1 R30.1 R58.1 U18.6 | length 2405.3
  Top Layer w20: C43.1 R30.1 7035.12,2014.88 7070,1980 U18.6 7200,1980 7255,1925 7405,1925 7455,1875 v1(7455,1475) ; v1(7645,1475) 7745,1475 7810,1410 7810,970 7920,860 R58.1
  Bottom Layer w20: v1(7455,1475) v1(7645,1475)
NetC43_2: C43.2 R8.1 R30.2 R44.1 R59.1 U18.2 | length 701.2
  Top Layer w20: R59.1 6770,1900 6805.12,1935.12 R8.1 ; C43.2 R30.2 6884.88,2160 R44.1 R8.1 ; U18.2 R8.1
NetC44_1: C44.1 R43.1 U14.5 | length 240.7
  Top Layer w20: R43.1@3190,840.12 U14.5
NetC44_2: C44.2 R38.1 U14.3 | length 235.7
  Top Layer w20: R38.1@3090,845.12 U14.3
NetC45_1: C45.1 D5.1 Q3.1 R37.1 R41.1 R42.2 U15.1 | length 1364.7
  Top Layer w20: Q3.1 11150.12,2424.88 R41.1 R42.2 R37.1 11734.88,2090.12 11800,2025 U15.1 ; D5.1 R41.1@11258.07,2422.95
NetC46_1: C46.1 D6.1 Q3.2 R41.2 | length 1556.8
  Top Layer w20: D6.1 11155,2075 11075,2155 Q3.2 11074.88,2424.88 C46.1 10855.12,2424.88 10810,2470 10810,2655 10845,2690 11230,2690 11260,2660 R41.2
NetC52_2: C52.2 D10.2 R48.1 R50.2 U16.1 | length 821.7
  Top Layer w20: C52.2 R48.1@8541.69,3638.43 ; R48.1 R50.2 8798.19,3635.12 8798.19,3848.19 8815,3865 U16.1
NetC53_1: C53.1 D11.1 R49.1 R51.2 U17.1 | length 1496.9
  Top Layer w20: U17.1 6960,3790 6995,3755 6995,3525 7021.61,3498.39 D11.1 7070,3380 7100,3350 7265,3350 7335,3420 R51.2 R49.1 7470,3455 7498.43,3426.57 C53.1
NetC54_2: C54.2 U18.5 | length 119.6
  Top Layer w20: C54.2@7129.49,1810.39 U18.5
NetD1_1: D1.1 R3.1 | length 129.9
  Top Layer w20: D1.1 R3.1
NetD1_4: D1.4 R2.2 | length 290.6
  Top Layer w20: D1.4 12065,175 12115,225 R2.2
NetD2_1: D2.1 D3.2 L1.2 M1.3 Q2.2 R39.1 | length 8843.7
  Top Layer w15: M1.3 2400,2820 2430,2850 v1(2435,2850)
  Top Layer w20: v1(5860,1300) 5860,1160 5896.93,1123.07 D3.2 ; D2.1 6281.93,1266.93 6300,1285 v1(6300,1300)
  Top Layer w40: Q2.2 2810,3770 2970,3930 3600,3930 3895,3635 5590,3635 6365,2860 6365,2540 6250,2425 6250,1765 6110,1625 6110,1400 6190,1320 ; D2.1 6190,1320 ; R39.1 7025,1305 6935,1395 L1.2 6265,1395 6190,1320
  Bottom Layer w15: v1(2435,2850) 2435,3100 2580,3245 2710,3245 2810,3345 Q2.2
  Bottom Layer w20: v1(5860,1300) v1(6300,1300)
NetD7_A: D7.A R36.2 | length 309.9
  Top Layer w20: D7.A R36.2
NetD12_2: D12.2 Q1.1 R40.1 | length 1416.4
  Top Layer w20: Q1.1 4851.26,1498.74 4830,1520 4830,1620 4875,1665 5350,1665 5410.12,1604.88 R40.1 5461.93,1163.19 D12.2
NetD13_2: D13.2 Q2.1 R22.1 | length 1172.7
  Top Layer w20: D13.2 2505,3085 2520,3070 ; R22.1@2520,2870.12 2520,3070 ; v1(2595,3145) 2520,3070
  Bottom Layer w20: v1(2595,3145) 2735,3145 2910,3320 Q2.1
NetJ2_1: J2.1 R16.1 | length 318.1
  Top Layer w20: R16.1 6385.12,629.88 6441,574 J2.1
NetJ3_1: J3.1 R34.2 R38.2 | length 311.7
  Top Layer w20: R38.2 3070,704.88 3070,519 J3.1
NetJ3_6: J3.6 R43.2 R45.1 | length 384.9
  Top Layer w15: J3.6 R45.1@3208,593.12
  Top Layer w20: R45.1@3210,595.12 R43.2
NetJ4_1: J4.1 R54_DD1.2 | length 1509.3
  Top Layer w20: R54_DD1.2 10115,1350 10186,1279 J4.1
NetJ4_2: J4.2 R54_DD2.2 | length 2198
  Top Layer w20: R54_DD2.2 9115,1375 9205,1285 9750,1285 10078,957 J4.2
NetJ4_3: J4.3 R54_DD3.2 | length 3074.2
  Top Layer w20: R54_DD3.2 8115,1260 8270,1105 8650,1105 9680,1105 9970,815 J4.3
NetJ4_6: J4.6 R57_DD1.2 | length 1661.9
  Top Layer w20: R57_DD1.2 9975,1365 10132,1208 J4.6
NetJ4_7: J4.7 R57_DD2.2 | length 2379.9
  Top Layer w20: R57_DD2.2 8975,1370 9135,1210 9730,1210 10024,916 J4.7
NetJ4_8: J4.8 R57_DD3.2 | length 3250.3
  Top Layer w20: R57_DD3.2 7975,1280 8200,1055 8500,1055 9650,1055 9916,789 J4.8
NetM1_2: M1.2 R22.2 R60.1 | length 254.9
  Top Layer w15: R60.1@2419.69,2575.43 M1.2 R22.2@2507.56,2742.44
NetP2_1: P2.1 R7.1 | length 692.2
  Top Layer w20: R7.1 4325,580 4415,490 P2.1
NetP2_2: P2.2 R5.2 | length 1073.9
  Top Layer w20: R5.2 4195,495 4285,405 4840,405 4868.43,433.43 P2.2
NetP3_1: P3.1 R13.2 | length 329.9
  Top Layer w20: P3.1 R13.2
NetP4_1: P4.1 R58.2 | length 594.2
  Top Layer w20: R58.2 8475,860 8570,765 P4.1
NetP5_1: P5.1 R61.1 | length 184.9
  Top Layer w20: R61.1 P5.1
NetP6_1: P6.1 R62.1 | length 189.9
  Top Layer w20: R62.1 P6.1
NetQ1_3: Q1.3 W1.2 | length 277.1
  Top Layer w20: Q1.3 4991.26,1591.26 v1(5015,1615)
  Bottom Layer w20: W1.2 4925,1705 v1(5015,1615)
NetQ4_1: Q4.1 R1.1 R14.1 R15.3 R25.3 TP1.1 | length 9448.8
  Top Layer w20: R25.3 R15.3 2340,240 2465,115 3985,115 4075,205 4075,605 3815,865 3815,1525 4000,1710 4705,1710 ; R14.1 4765,1540 4705,1600 4705,1710 ; R1.1 5551.57,2991.57 5610,3050 5945,3050 6155,2840 6155,2590 6140,2575 Q4.1 6100,2365 5985,2250 TP1.1 5795,2055 5700,1960 4865,1960 4705,1800 4705,1710
NetQ4_2: Q4.2 R6.1 | length 124.9
  Top Layer w20: R6.1@5900.12,2575 Q4.2
NetR1_2: R1.2 U1.2 | length 333.3
  Top Layer w20: R1.2 5381.46,2910 5361.46,2890 5361.46,2775 5401.46,2735 U1.2
NetR6_2: R6.2 U1.6 | length 232
  Top Layer w20: U1.6 R6.2@5899.88,2685
NetR11_1: R11.1 R27.1 R59.2 TP10.1 U10.6 | length 4053.4
  Top Layer w20: R11.1 3774.88,2669.88 3705.12,2600.12 R27.1 3705.12,2314.88 3740,2280 U10.6 3955,2280 4040,2195 TP10.1 v1(3875,1900) ; v1(6475,1900) R59.2
  Bottom Layer w20: v1(3875,1900) v1(6475,1900)
NetR15_2: R15.2 U6.3 | length 255.5
  Top Layer w20: R15.2 U6.3
NetR17_1: R17.1 W2.2 | length 906.2
  Top Layer w20: W2.2 1880,1420 1995,1535 2495,1535 2540,1580 R17.1
NetR17_2: R17.2 R18.1 R20.2 R26.2 U7.2 | length 554.9
  Top Layer w20: R18.1@2380.12,1889.76 R20.2 R26.2@2664.88,1755 ; R17.2 U7.2
NetR18_2: R18.2 R21.1 U7.6 | length 605.4
  Top Layer w20: R21.1 R18.2@2379.88,2000 ; R18.2 2575.12,2000.12 2590,2015 U7.6
NetR19_1: R19.1 TP9.1 U6.6 W2.1 | length 837.4
  Top Layer w20: R19.1 1740.12,985.12 1770,1015 U6.6 W2.1 TP9.1
NetR19_2: R19.2 U6.2 | length 305.2
  Top Layer w20: R19.2 1560,830 1595,795 1695,795 1720,820 U6.2
NetR20_1: R20.1 W3.2 | length 1914.9
  Top Layer w20: W3.2 720,1420 780,1480 780,1670 865,1755 R20.1
NetR23_1: R23.1 R28.1 U8.6 | length 599.2
  Top Layer w20: R23.1@1780,2650 1780,2540 1815.12,2504.88 R28.1 1870,2315.12 1870,2190 1900,2160 U8.6
NetR24_1: R24.1 U11.6 | length 336.6
  Top Layer w20: R24.1 3059.88,2290.12 3100,2250 U11.6
NetR25_2: R25.2 U12.3 | length 255.5
  Top Layer w20: R25.2 U12.3
NetR26_1: R26.1 W4.2 | length 1721.5
  Top Layer w20: R26.1 2764.88,1644.88 2810,1690 2810,1885 2875,1950 3620,1950 3715,1855 3715,1655 3675,1615 W4.2
NetR27_2: R27.2 U10.2 | length 316.1
  Top Layer w20: R27.2 3535,2490 3505,2460 3505,2350 3525,2330 U10.2
NetR28_2: R28.2 U8.2 | length 243.2
  Top Layer w20: R28.2 1680,2345.12 1680,2240 1710,2210 U8.2
NetR29_1: R29.1 TP11.1 U12.6 W3.1 | length 832.4
  Top Layer w20: R29.1 570.12,990.12 600,1020 U12.6 W3.1@600,1315 ; W3.1 TP11.1
NetR29_2: R29.2 U12.2 | length 318.2
  Top Layer w20: R29.2 385,820 410,795 520,795 550,825 U12.2
NetR32_2: R32.2 U13.2 | length 308.2
  Top Layer w20: R32.2 2625,4295 2600,4270 2600,4175 2630,4145 U13.2
NetR33_1: R33.1 R35.1 U14.12 | length 293.2
  Top Layer w20: R35.1 R33.1 3190,1574.88 U14.12
NetR33_2: R33.2 U14.1 U14.2 | length 1803.7
  Top Layer w20: U14.1 2990,1015 ; U14.2 3040,1015 3025,1000 3005,1000 2990,1015 ; R33.2 3160,1815 3130,1845 2895,1845 2860,1810 2860,1650 2670,1460 2670,1055 2725,1000 2975,1000 2990,1015
NetR46_1: R46.1 TP14.1 U14.10 W4.1 | length 1010.6
  Top Layer w20: U14.10 3290,1315 3345,1260 TP14.1 3520,1365 3465,1420 3465,1712.56 3462.56,1715 ; R46.1@3385.12,1715 3462.56,1715 ; W4.1 3462.56,1715
NetR46_2: R46.2 R47.1 U14.11 | length 290.2
  Top Layer w20: U14.11 3240,1569.88 R47.1 R46.2
NetR47_2: R47.2 U14.6 U14.7 | length 1426.2
  Top Layer w20: U14.6 3240,1015 3260,995 3275,995 3290,1010 ; R47.2 3275,1825 3305,1855 v1(3330,1855) ; U14.7 3290,1010 ; v1(3445,1010) 3290,1010
  Bottom Layer w20: v1(3330,1855) 3445,1740 v1(3445,1010)
NetR52_DD1_1: R52_DD1.1 R53_DD1.2 U19_DD1.2 | length 245.4
  Top Layer w20: U19_DD1.2 10249.88,2185 R53_DD1.2@10249.88,2295
NetR52_DD1_2: R52_DD1.2 R54_DD1.1 TP18_DD1.1 U19_DD1.1 | length 574.2
  Top Layer w20: R54_DD1.1@10114.49,2020.63 U19_DD1.1 ; R54_DD1.1 10239.88,2020.12 TP18_DD1.1 10360.12,2020.12 R52_DD1.2@10360.12,2185
NetR52_DD2_1: R52_DD2.1 R53_DD2.2 U19_DD2.2 | length 245.4
  Top Layer w20: U19_DD2.2 9249.88,2185 R53_DD2.2@9249.88,2295
NetR52_DD2_2: R52_DD2.2 R54_DD2.1 TP18_DD2.1 U19_DD2.1 | length 574.2
  Top Layer w20: R54_DD2.1@9114.49,2020.63 U19_DD2.1 ; R54_DD2.1 9239.88,2020.12 TP18_DD2.1 9360.12,2020.12 R52_DD2.2@9360.12,2185
NetR52_DD3_1: R52_DD3.1 R53_DD3.2 U19_DD3.2 | length 245.4
  Top Layer w20: U19_DD3.2 8249.88,2185 R53_DD3.2@8249.88,2295
NetR52_DD3_2: R52_DD3.2 R54_DD3.1 TP18_DD3.1 U19_DD3.1 | length 574.2
  Top Layer w20: R54_DD3.1@8114.49,2020.63 U19_DD3.1 ; R54_DD3.1 8239.88,2020.12 TP18_DD3.1 8360.12,2020.12 R52_DD3.2@8360.12,2185
NetR55_DD1_1: R55_DD1.1 R56_DD1.2 U19_DD1.6 | length 280.4
  Top Layer w20: R56_DD1.2@9790.12,2380 9790.12,2235 U19_DD1.6
NetR55_DD1_2: R55_DD1.2 R57_DD1.1 TP19_DD1.1 U19_DD1.7 | length 766.7
  Top Layer w20: R55_DD1.2 9674.88,2175.12 9705,2145 ; TP19_DD1.1 9705,2145 ; R57_DD1.1 10010,2060.12 10010,2165 9990,2185 U19_DD1.7 9860,2185 9820,2145 9705,2145
NetR55_DD2_1: R55_DD2.1 R56_DD2.2 U19_DD2.6 | length 280.4
  Top Layer w20: R56_DD2.2@8790.12,2380 8790.12,2235 U19_DD2.6
NetR55_DD2_2: R55_DD2.2 R57_DD2.1 TP19_DD2.1 U19_DD2.7 | length 766.7
  Top Layer w20: R55_DD2.2 8674.88,2175.12 8705,2145 ; TP19_DD2.1 8705,2145 ; R57_DD2.1 9010,2060.12 9010,2165 8990,2185 U19_DD2.7 8860,2185 8820,2145 8705,2145
NetR55_DD3_1: R55_DD3.1 R56_DD3.2 U19_DD3.6 | length 280.4
  Top Layer w20: R56_DD3.2@7790.12,2380 7790.12,2235 U19_DD3.6
NetR55_DD3_2: R55_DD3.2 R57_DD3.1 TP19_DD3.1 U19_DD3.7 | length 766.7
  Top Layer w20: R55_DD3.2 7674.88,2175.12 7705,2145 ; TP19_DD3.1 7705,2145 ; R57_DD3.1 8010,2060.12 8010,2165 7990,2185 U19_DD3.7 7860,2185 7820,2145 7705,2145
NetU14_15: U14.15 U14.16 | length 217.4
  Top Layer w20: U14.16 2990,1510 3017.5,1537.5 3040,1515 U14.15
pads on no net: D7.0 J2.2 J2.4 J2.6 J2.8 J2.9 J3.2 J3.3 J3.4 J3.5 J3.7 J3.8 J3.9 J4.4 J4.5 J4.9 P2.3 P2.4 P3.3 P3.4 P4.3 P4.4 Q2.4 Q2.5 R31.4 R31.5 SW1.3 SW1.4 SW1.5 U1.1 U1.5 U1.8 U2.1 U2.8 U3.1 U3.8 U4.1 U4.5 U4.8 U5.1 U5.8 U6.1 U6.5 U6.8 U7.1 U7.5 U7.8 U8.1 U8.5 U8.8 U9.1 U9.5 U9.8 U10.1 U10.5 U10.8 U11.1 U11.3 U11.5 U11.7 U11.8 U12.1 U12.5 U12.8 U13.1 U13.5 U13.8 U14.8 U14.9 U15.4 U15.5 U16.4 U16.5 U17.4 U17.5 U18.1 U18.8 W1.3 W2.3 W3.3 W4.3

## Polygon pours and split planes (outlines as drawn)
+15 on Internal Plane 1 (split plane): 12429.9,20.1 20.1,20.1 20.1,4479.9 12429.9,4479.9
GND on Internal Plane 2 (split plane): 12429.9,20.1 20.1,20.1 20.1,4479.9 12429.9,4479.9
-15 on Internal Plane 3 (split plane): 12429.9,20.1 20.1,20.1 20.1,4479.9 12429.9,4479.9
GND on Internal Plane 4 (split plane): 12429.9,20.1 20.1,20.1 20.1,4479.9 12429.9,4479.9

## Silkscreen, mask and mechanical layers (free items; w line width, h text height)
Top Overlay:
  region: 12035,3970 12035,2720 12410,2720 12410,3970
  lines w15: 420,1535 440,1535 460,1515 460,1415 460,1405 460,1395 480,1375 ; 505,1325 505,1420 ; 1595,1530 1615,1530 1635,1510 1635,1410 1635,1400 1635,1390 1655,1370 ; 1680,1320 1680,1415 ; 3620,1625 3620,1720 ; 4935,1845 5030,1845
  text "LF_Imon" at 3210,4095 h60
  text "POS LED" at 9775,4055 h150 r90
  text "GND" at 5630,4040 h150
  text "NEG LED" at 10270,4040 h150 r90
  text "DC PWR IN" at 11065,3650 h150
  text "GND" at 11270,3170 h60
  text "-18" at 11670,3165 h60
  text "+18" at 10835,3160 h60
  text "GND" at 7915,2925 h150
  text "-15" at 8785,2920 h60
  text "+15" at 7030,2910 h60
  text "Serial Number" at 11985,2765 h150 r90
  text "Laser Current Driver" at 255,2170 h150 r90
  text "High Stability, Low Noise" at 140,2095 h150 r90
  text "VrefNeg" at 5585,2090 h60
  text "ON" at 4930,1885 h60
  text "Vref" at 3930,1735 h60
  text "ON" at 3665,1640 h60
  text "MF Imon" at 7795,1560 h60
  text "LF Imon" at 8775,1560 h60
  text "LD Cathode Vmon" at 9550,1560 h60
  text "ON" at 290,1510 h60
  text "LD_Anode" at 10610,1510 h60
  text "ON" at 1465,1505 h60
  text "CoarseV" at 720,1180 h60
  text "FineV" at 1940,1175 h60
  text "D1200719-v5" at 160,860 h200 r90
  text "Total Imon" at 8300,630 h60
  text "HF Imon" at 7385,625 h60
  text "Hi Freq In" at 4495,605 h150
  text "DAC IN" at 3610,590 h150
  text "Analog Monitors" at 9550,590 h60
  text "Drive Out" at 5955,555 h150
  text "Soft Start" at 10830,390 h60 r90
  text "Fine" at 1515,250 h60 r90
  text "Coarse" at 335,195 h60 r90
  text "Drive Enabled" at 11340,70 h60 r90
  text "+/-15V" at 11755,65 h60 r90
Mechanical 1:
  the board outline again, w15
Mechanical 13:
  lines w15: 700,-1250 700,0 ; 1870,-1250 1870,0 ; 3370,-1250 3370,435 ; 4770,-1255 4770,490 ; 6225,-4370 6225,690 ; 7570,-1505 7570,490 ; 8570,-1290 8570,490 ; 9970,-1270 9970,430 ; 11020,-1275 11020,755 ; 11520,-1280 11520,0 ; 11970,-1280 11970,0

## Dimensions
7570,-1505 to 6225,690 on Mechanical 13
8570,-1290 to 6225,-4370 on Mechanical 13
4770,-1255 to 6225,690 on Mechanical 13
9970,-1270 to 6225,-4370 on Mechanical 13
11020,-1275 to 6225,-4370 on Mechanical 13
11520,-1280 to 6225,-4370 on Mechanical 13
11970,-1280 to 6225,-4370 on Mechanical 13
12450,0 to 6225,-4370 on Mechanical 13
3370,-1250 to 6225,690 on Mechanical 13
1870,-1250 to 6225,-4370 on Mechanical 13
700,-1250 to 6225,-4370 on Mechanical 13
0,0 to 6225,-4370 on Mechanical 13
